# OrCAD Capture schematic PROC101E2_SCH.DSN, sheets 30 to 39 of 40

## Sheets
30 19. TEST AUTOMATION: size C; title: TEST AUTOMATION
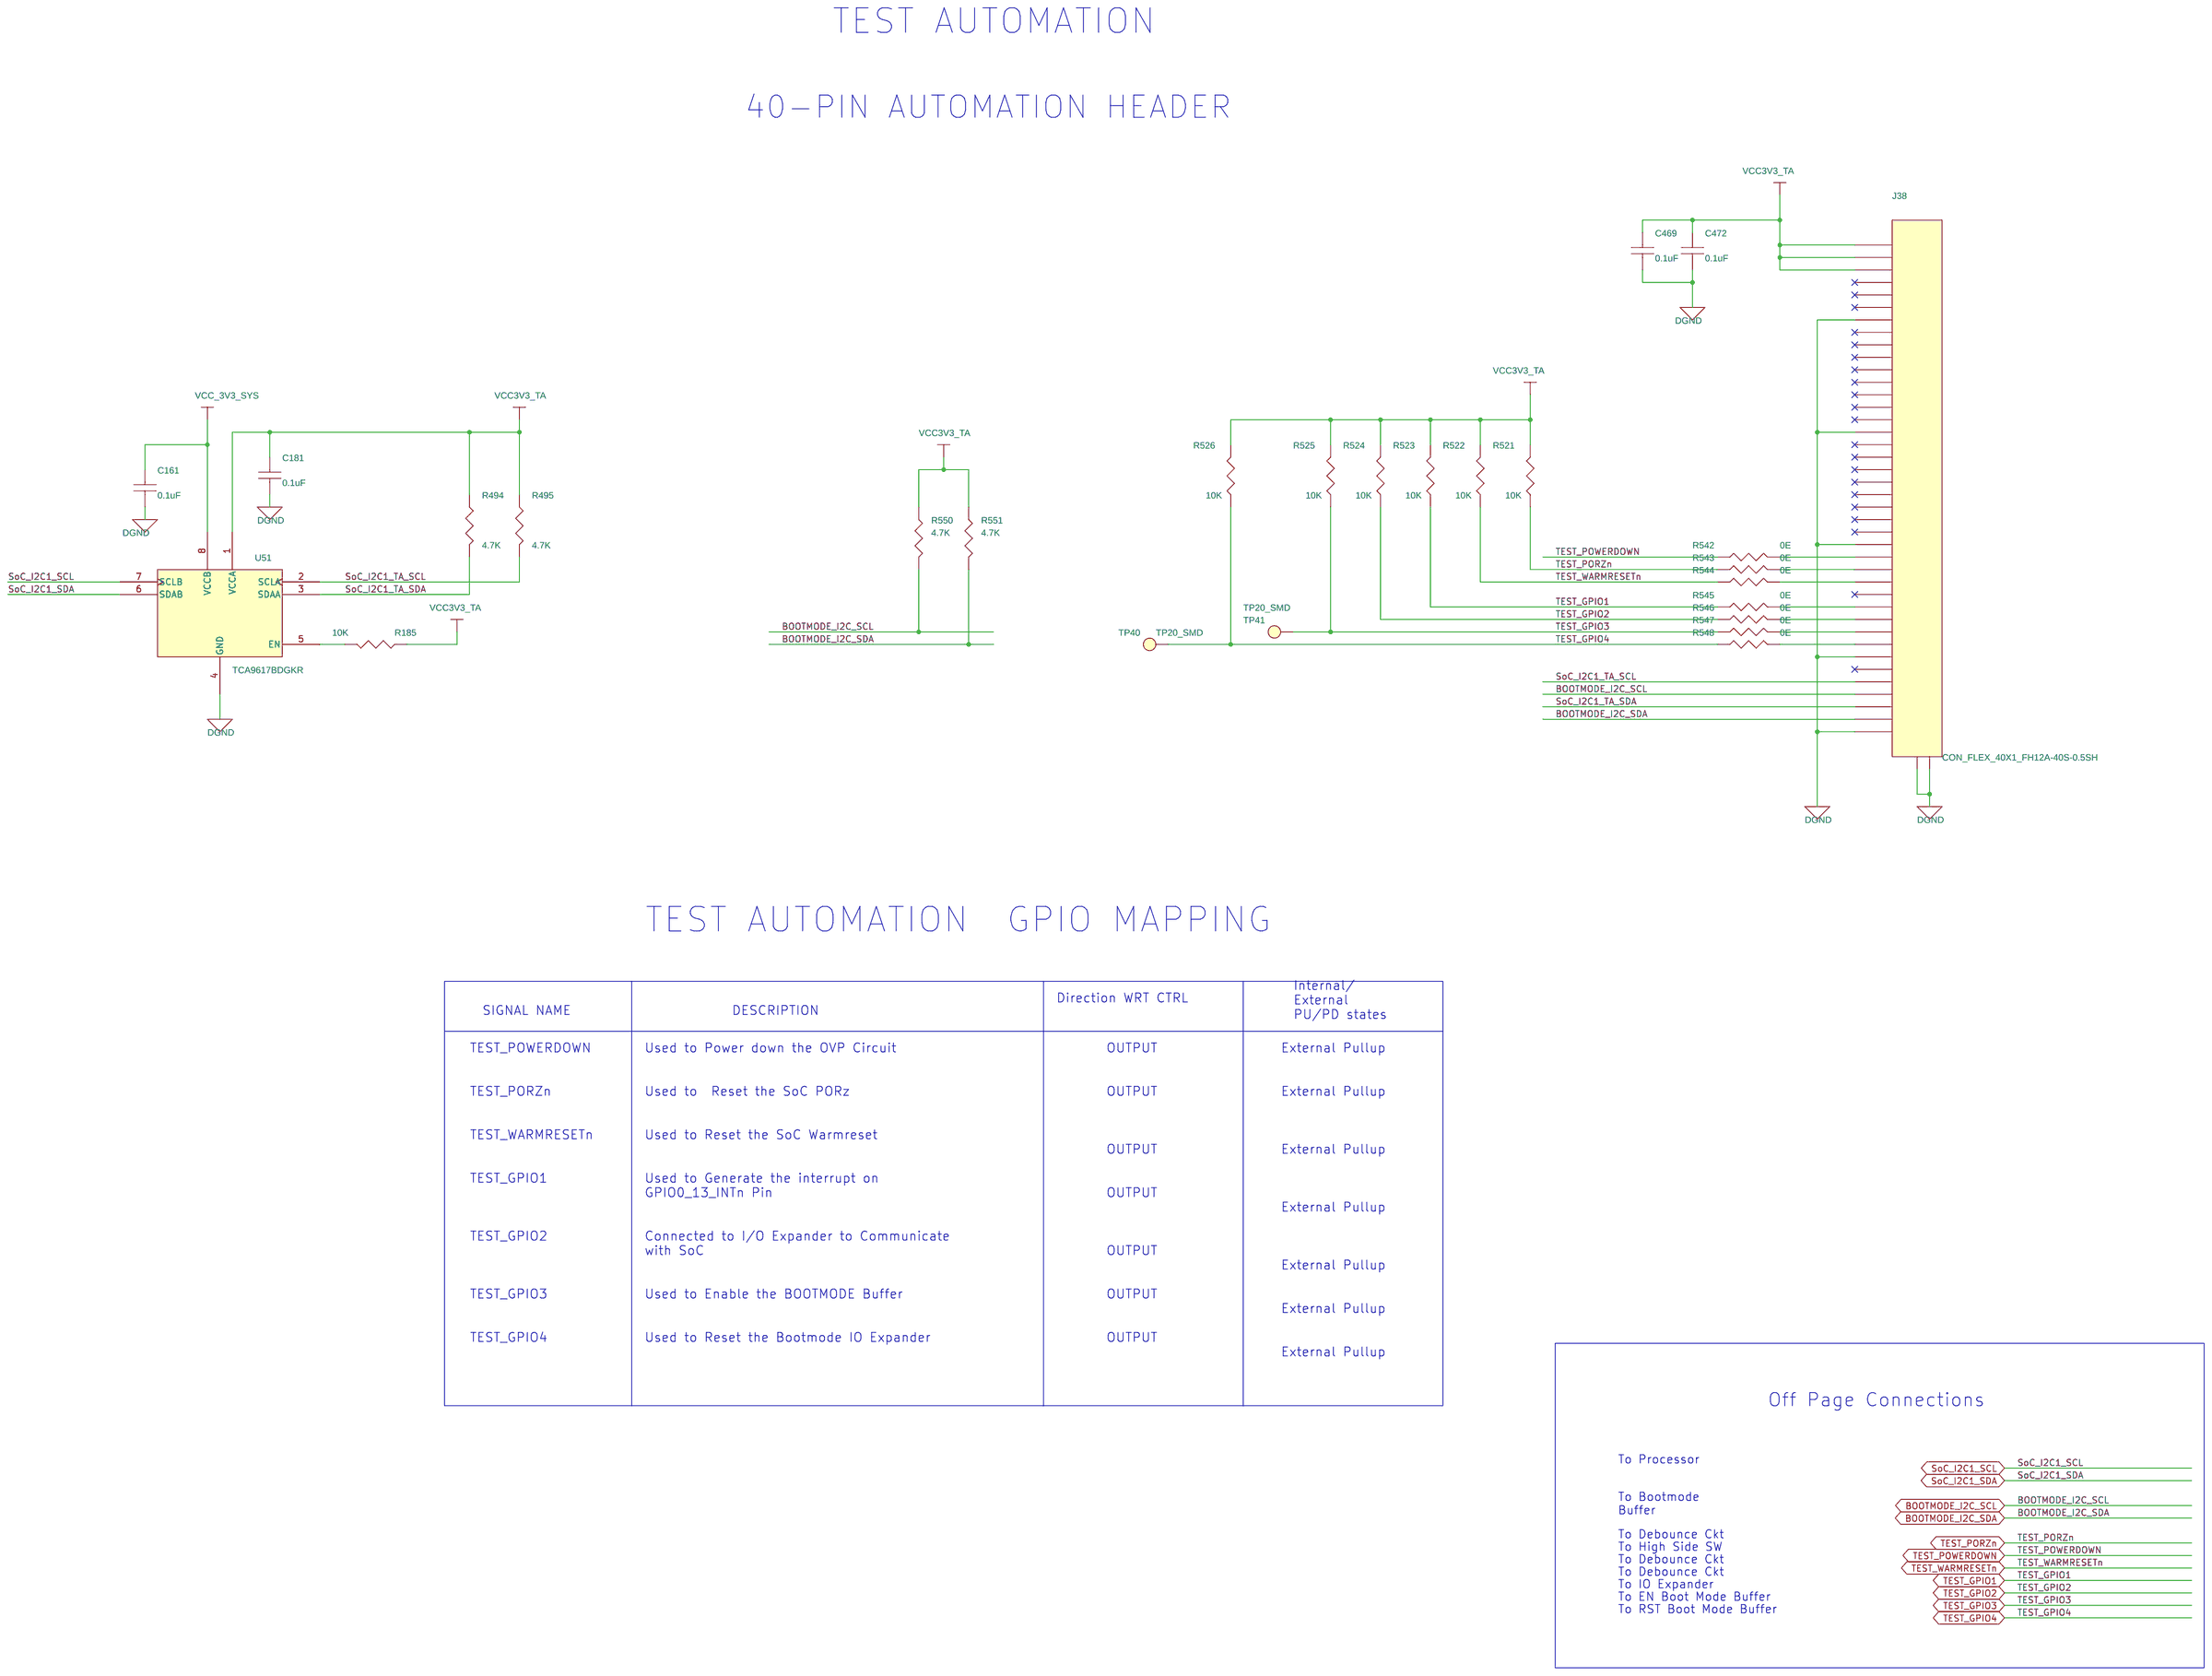
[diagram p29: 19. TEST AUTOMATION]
31 40. HARDWARE SCHEMATICS: title: HARDWARE SCHEMATICS
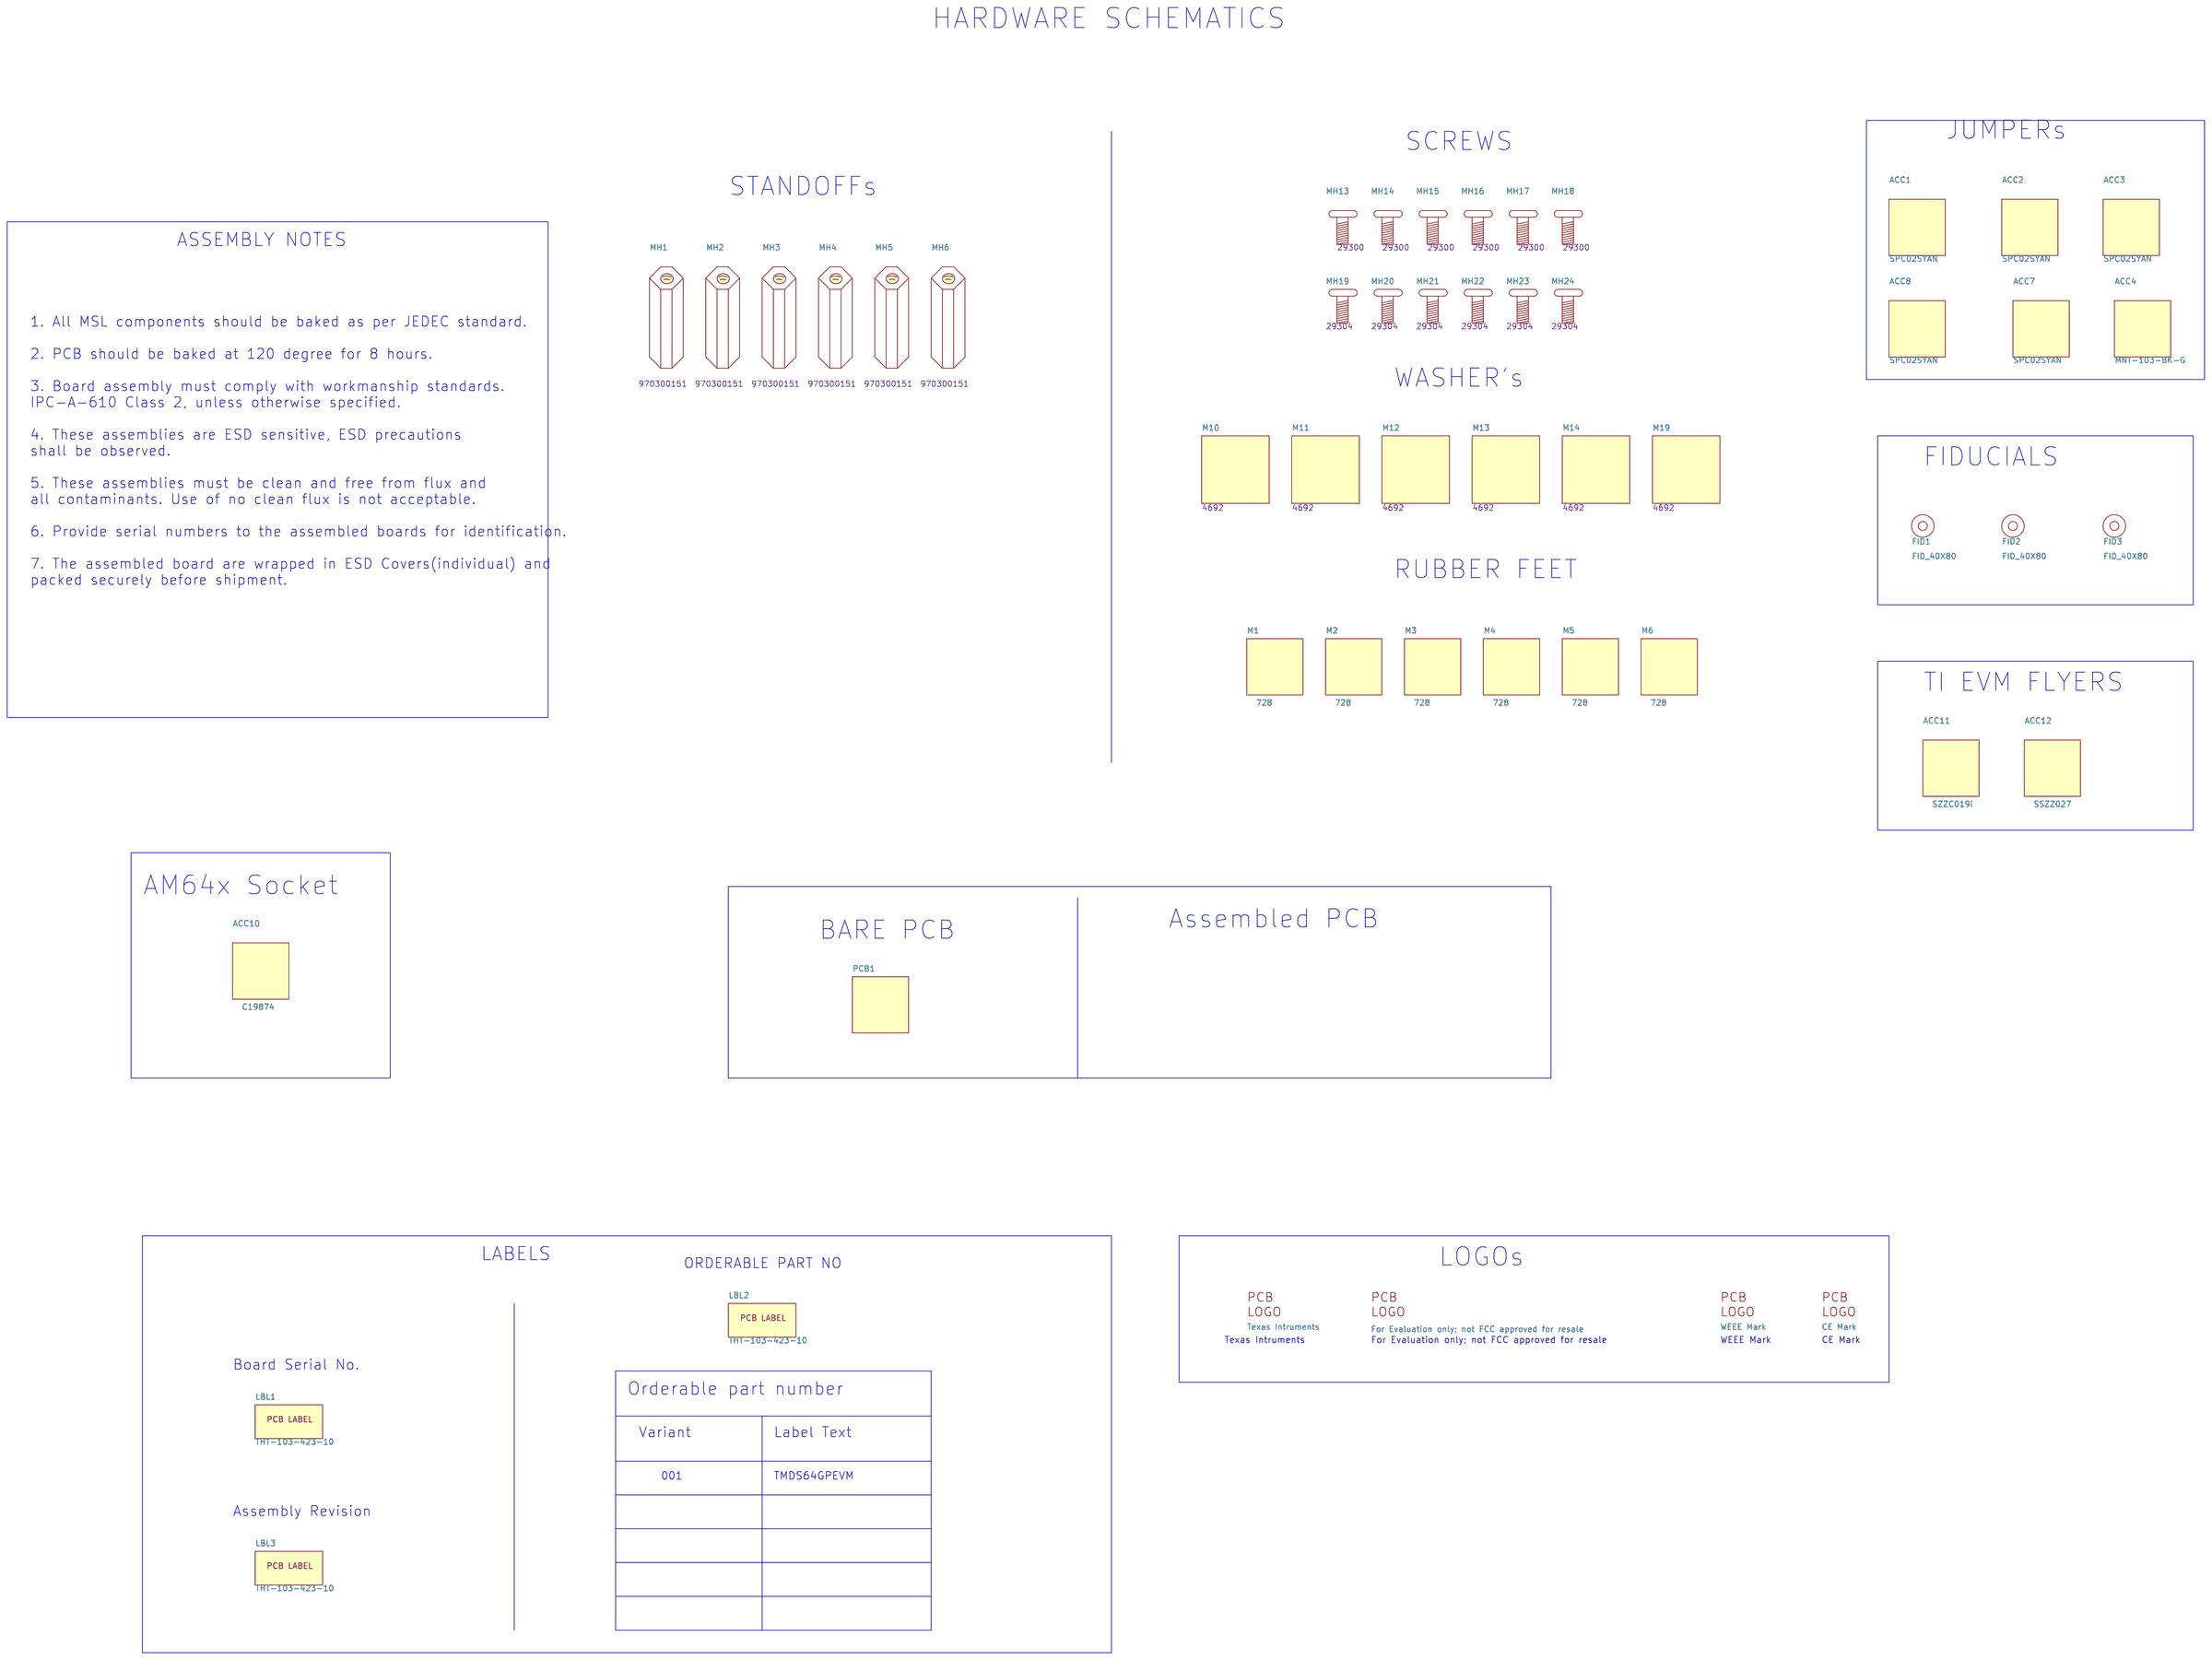
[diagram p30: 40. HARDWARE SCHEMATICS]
32 07. GPIO MAPPING TABLE: title: GPIO  MAPPING TABLE
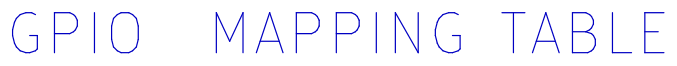
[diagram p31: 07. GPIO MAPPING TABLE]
33 08. I2C TREE: title: I2C TREE
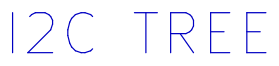
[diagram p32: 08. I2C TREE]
34 06. POWER SEQUENCE: title: POWER SEQUENCE
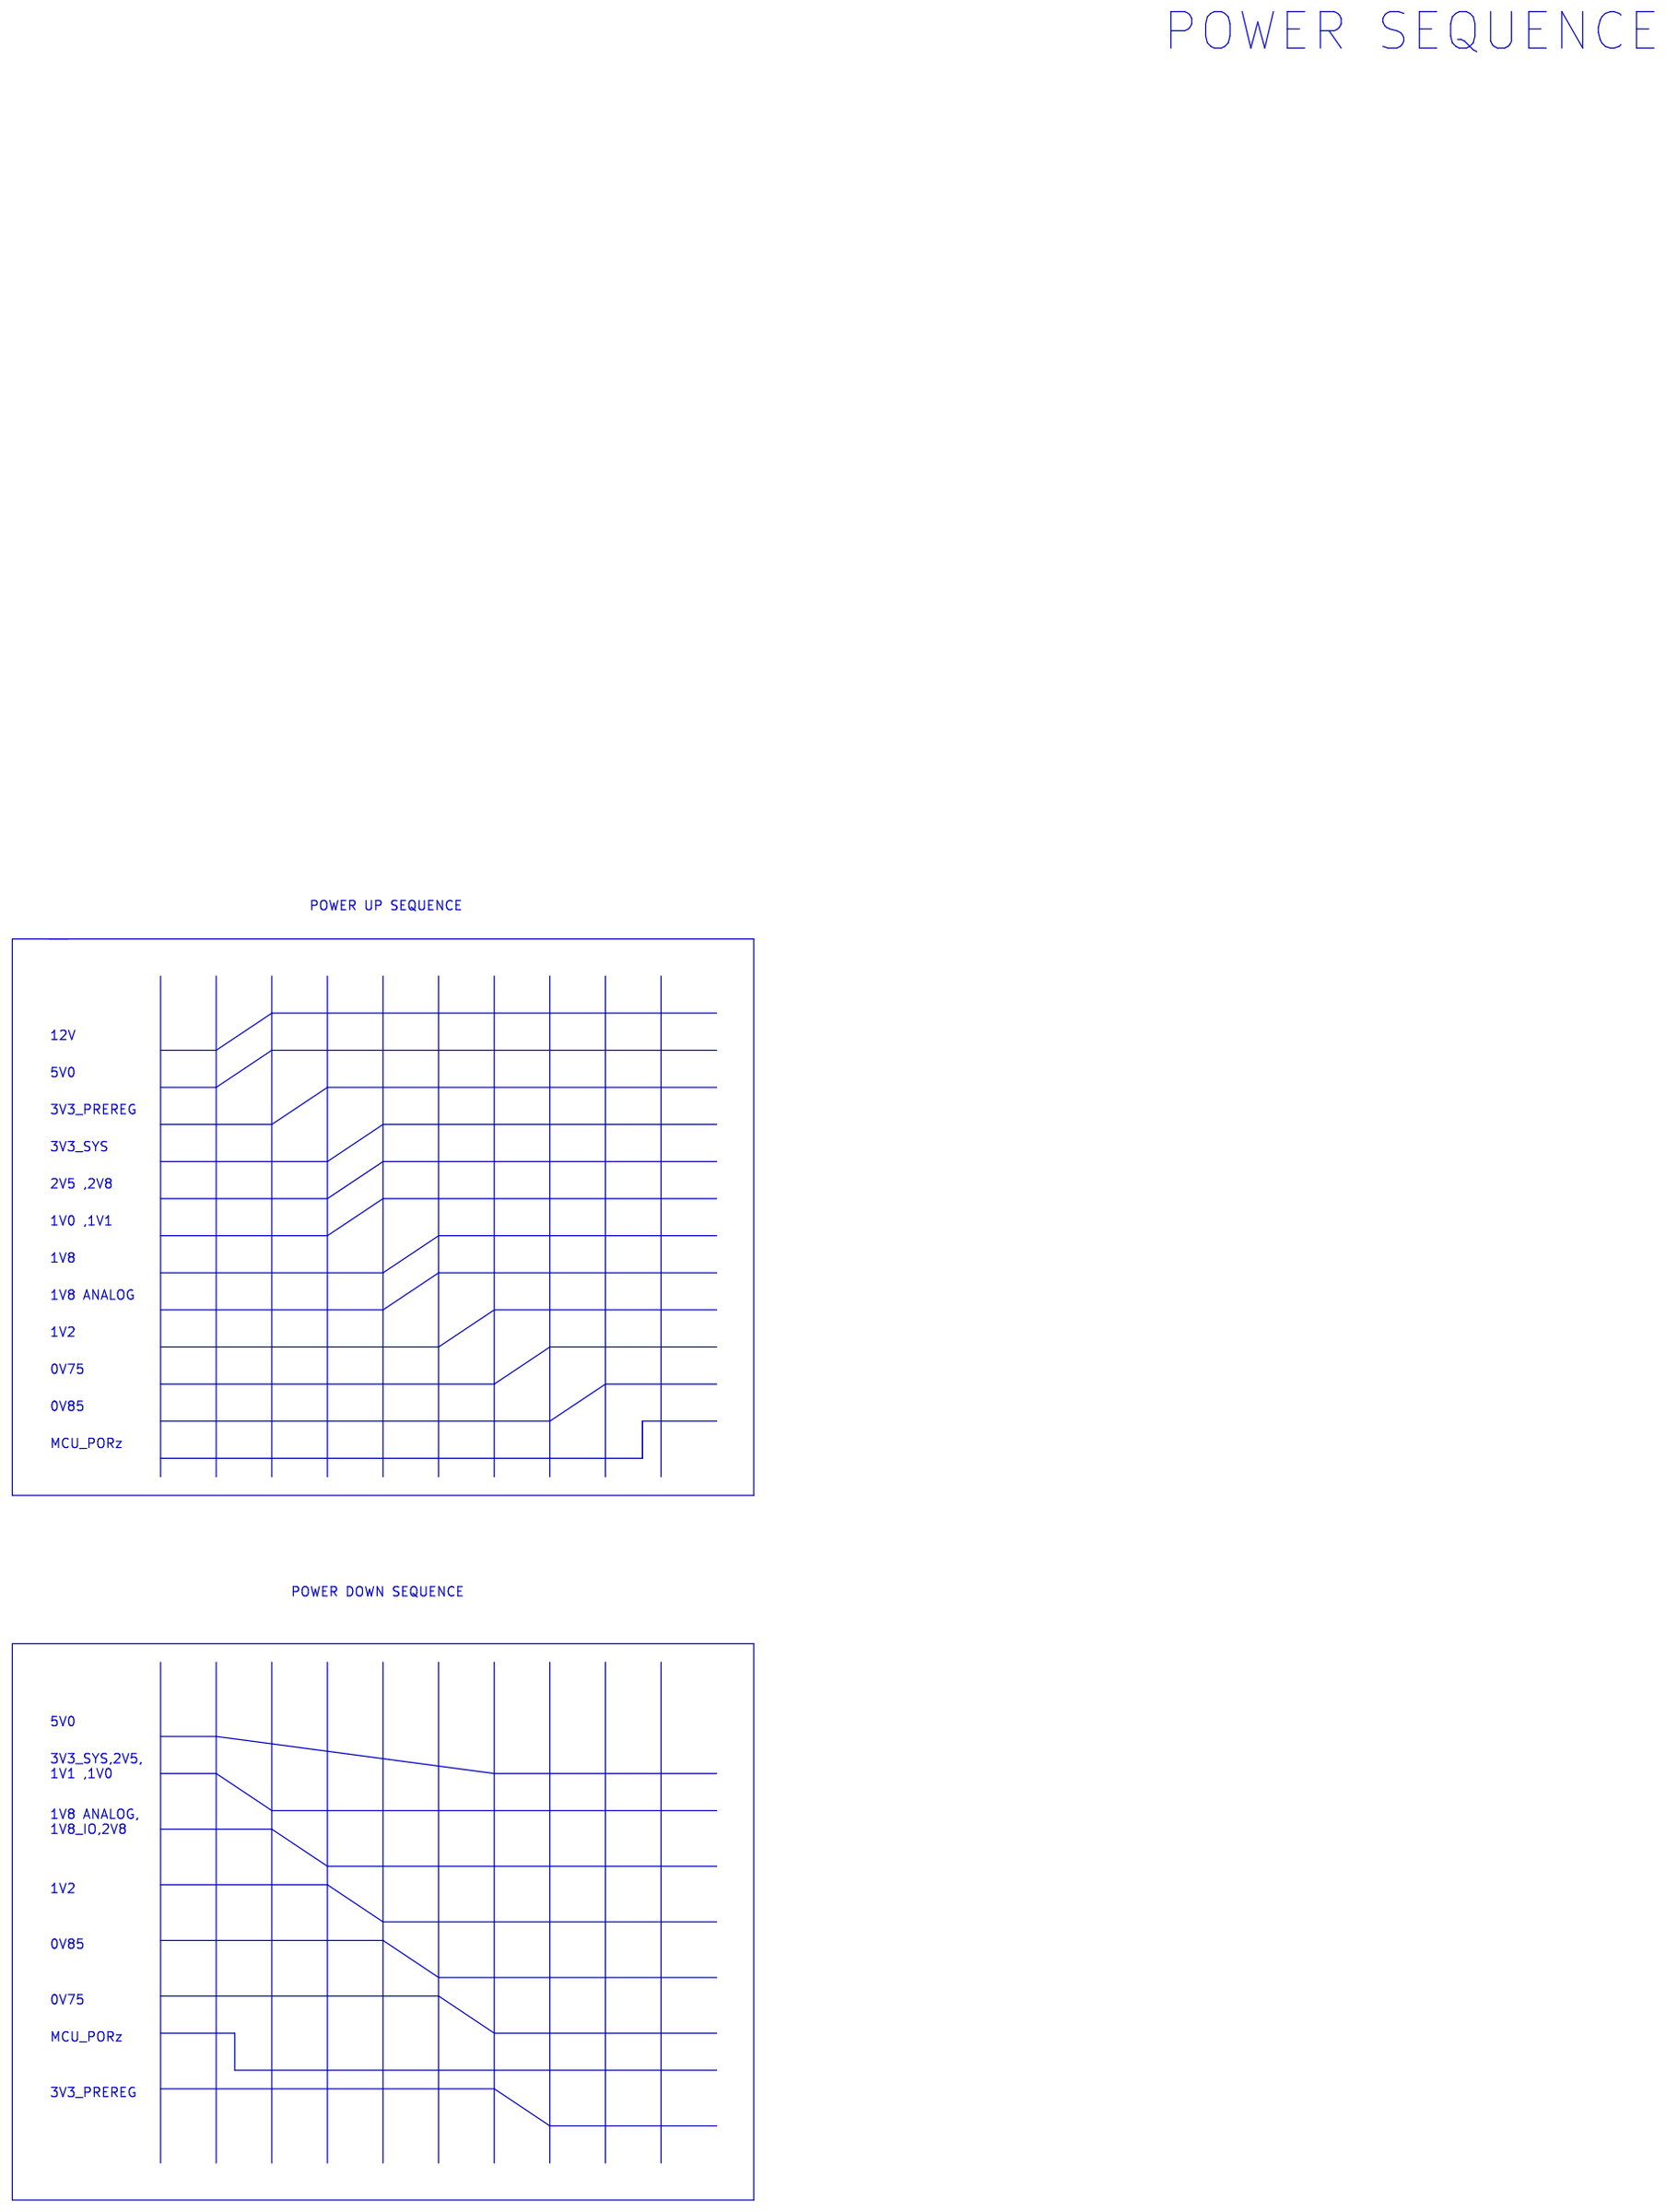
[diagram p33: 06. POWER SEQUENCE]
35 05. POWER FLOW DIAGRAM: title: POWER FLOW DIAGRAM
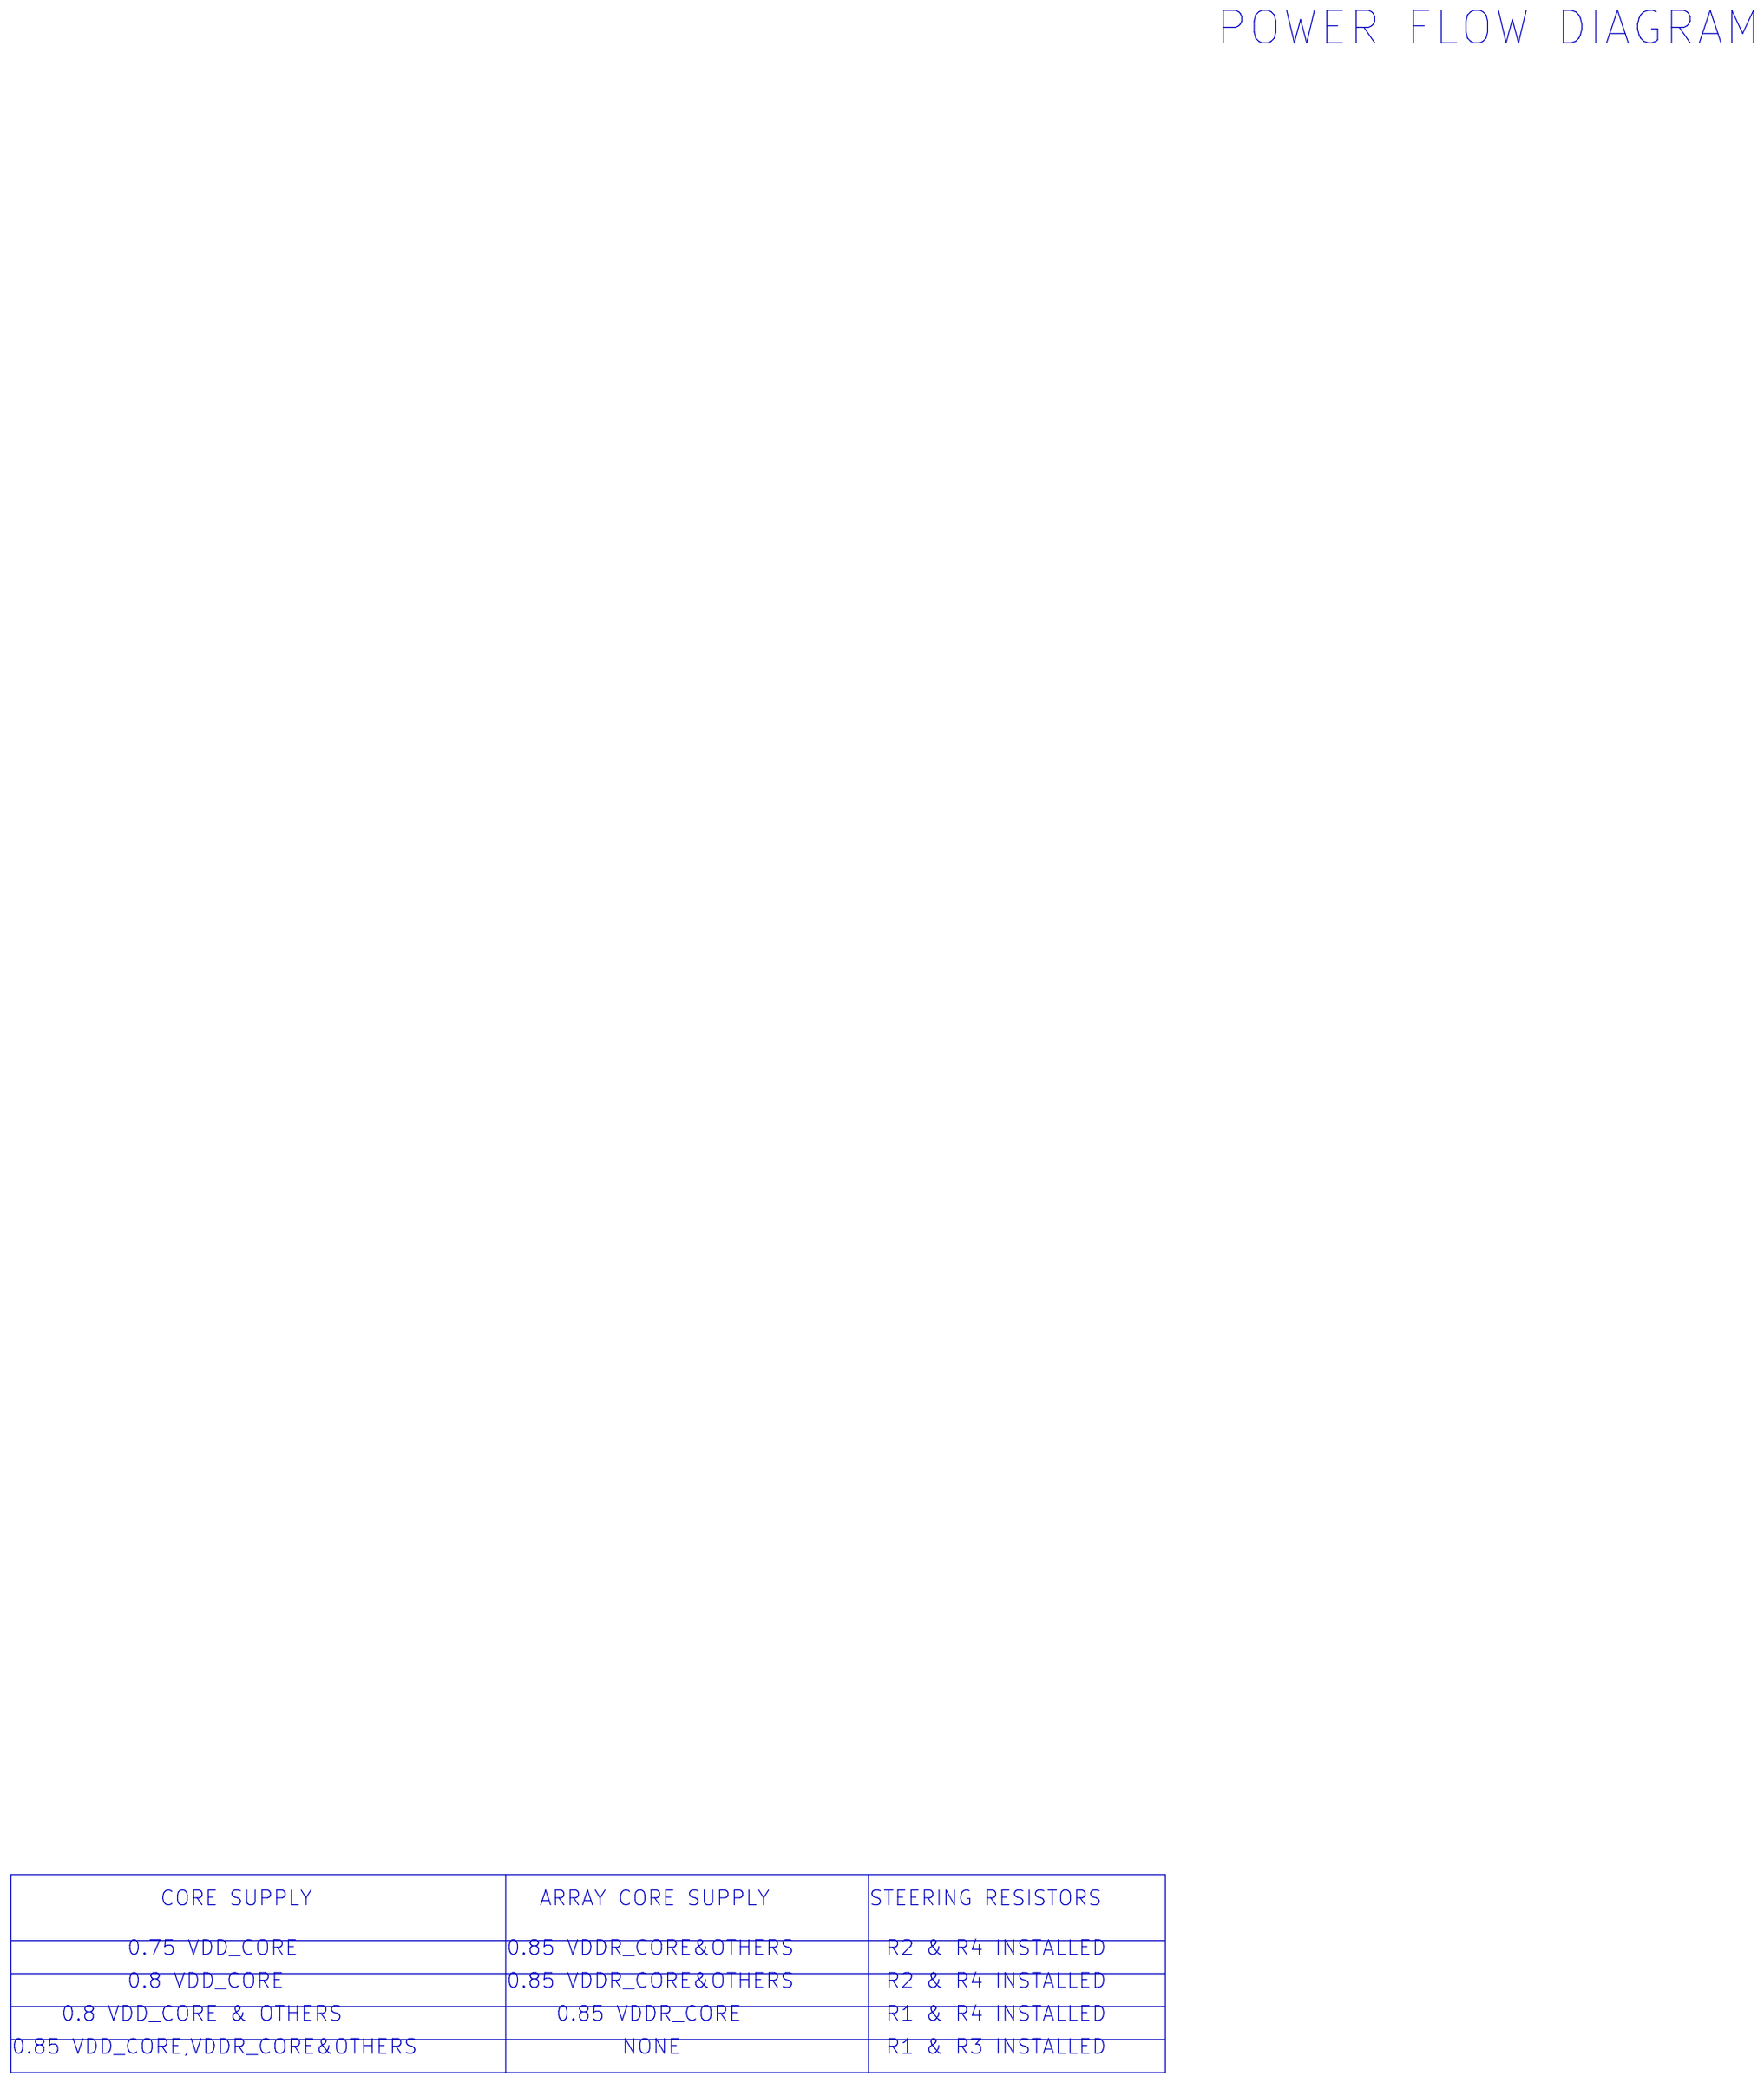
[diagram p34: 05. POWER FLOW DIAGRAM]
36 03.BLOCK_DIAGRAM_AM64x_EVM: title: BLOCK DIAGRAM_CP BOARD
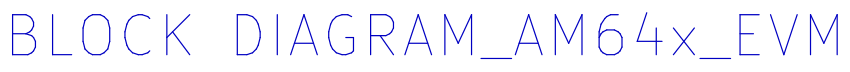
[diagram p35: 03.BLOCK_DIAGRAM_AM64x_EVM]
37 01. TABLE OF CONTENTS: title: TABLE OF CONTENTS
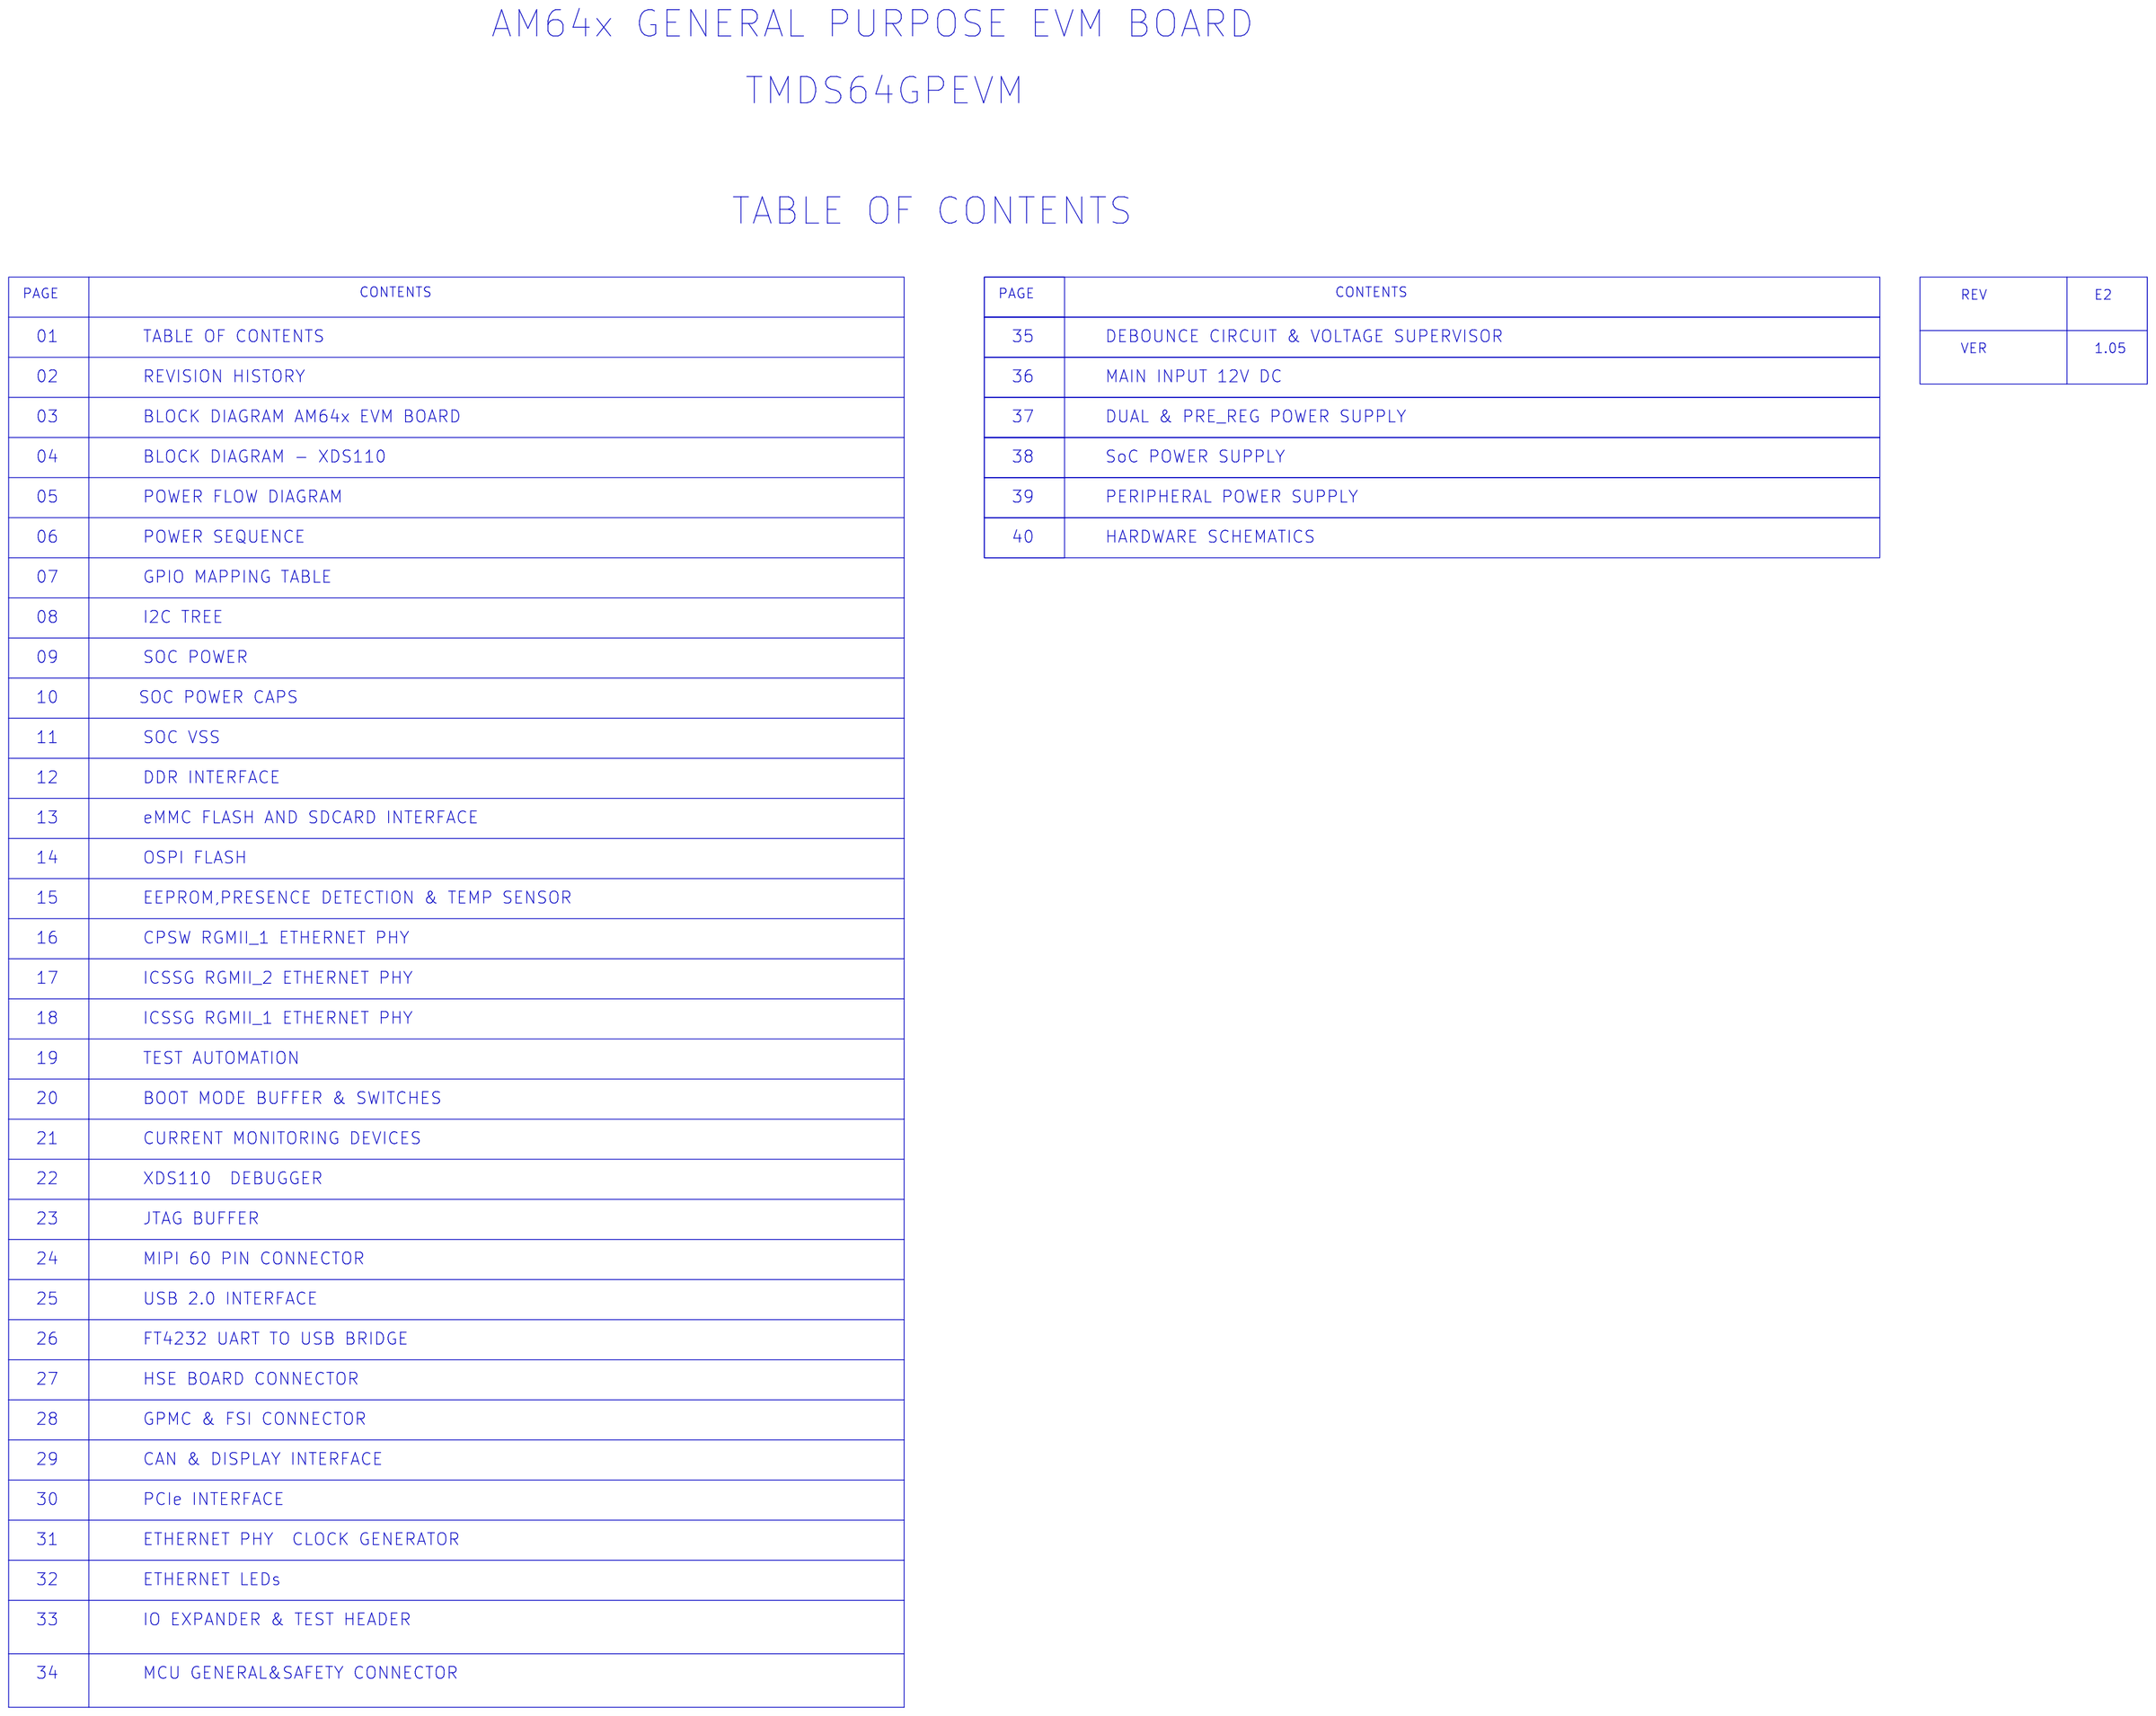
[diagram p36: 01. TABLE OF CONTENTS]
38 02. REVISION HISTORY: title: REVISION HISTORY
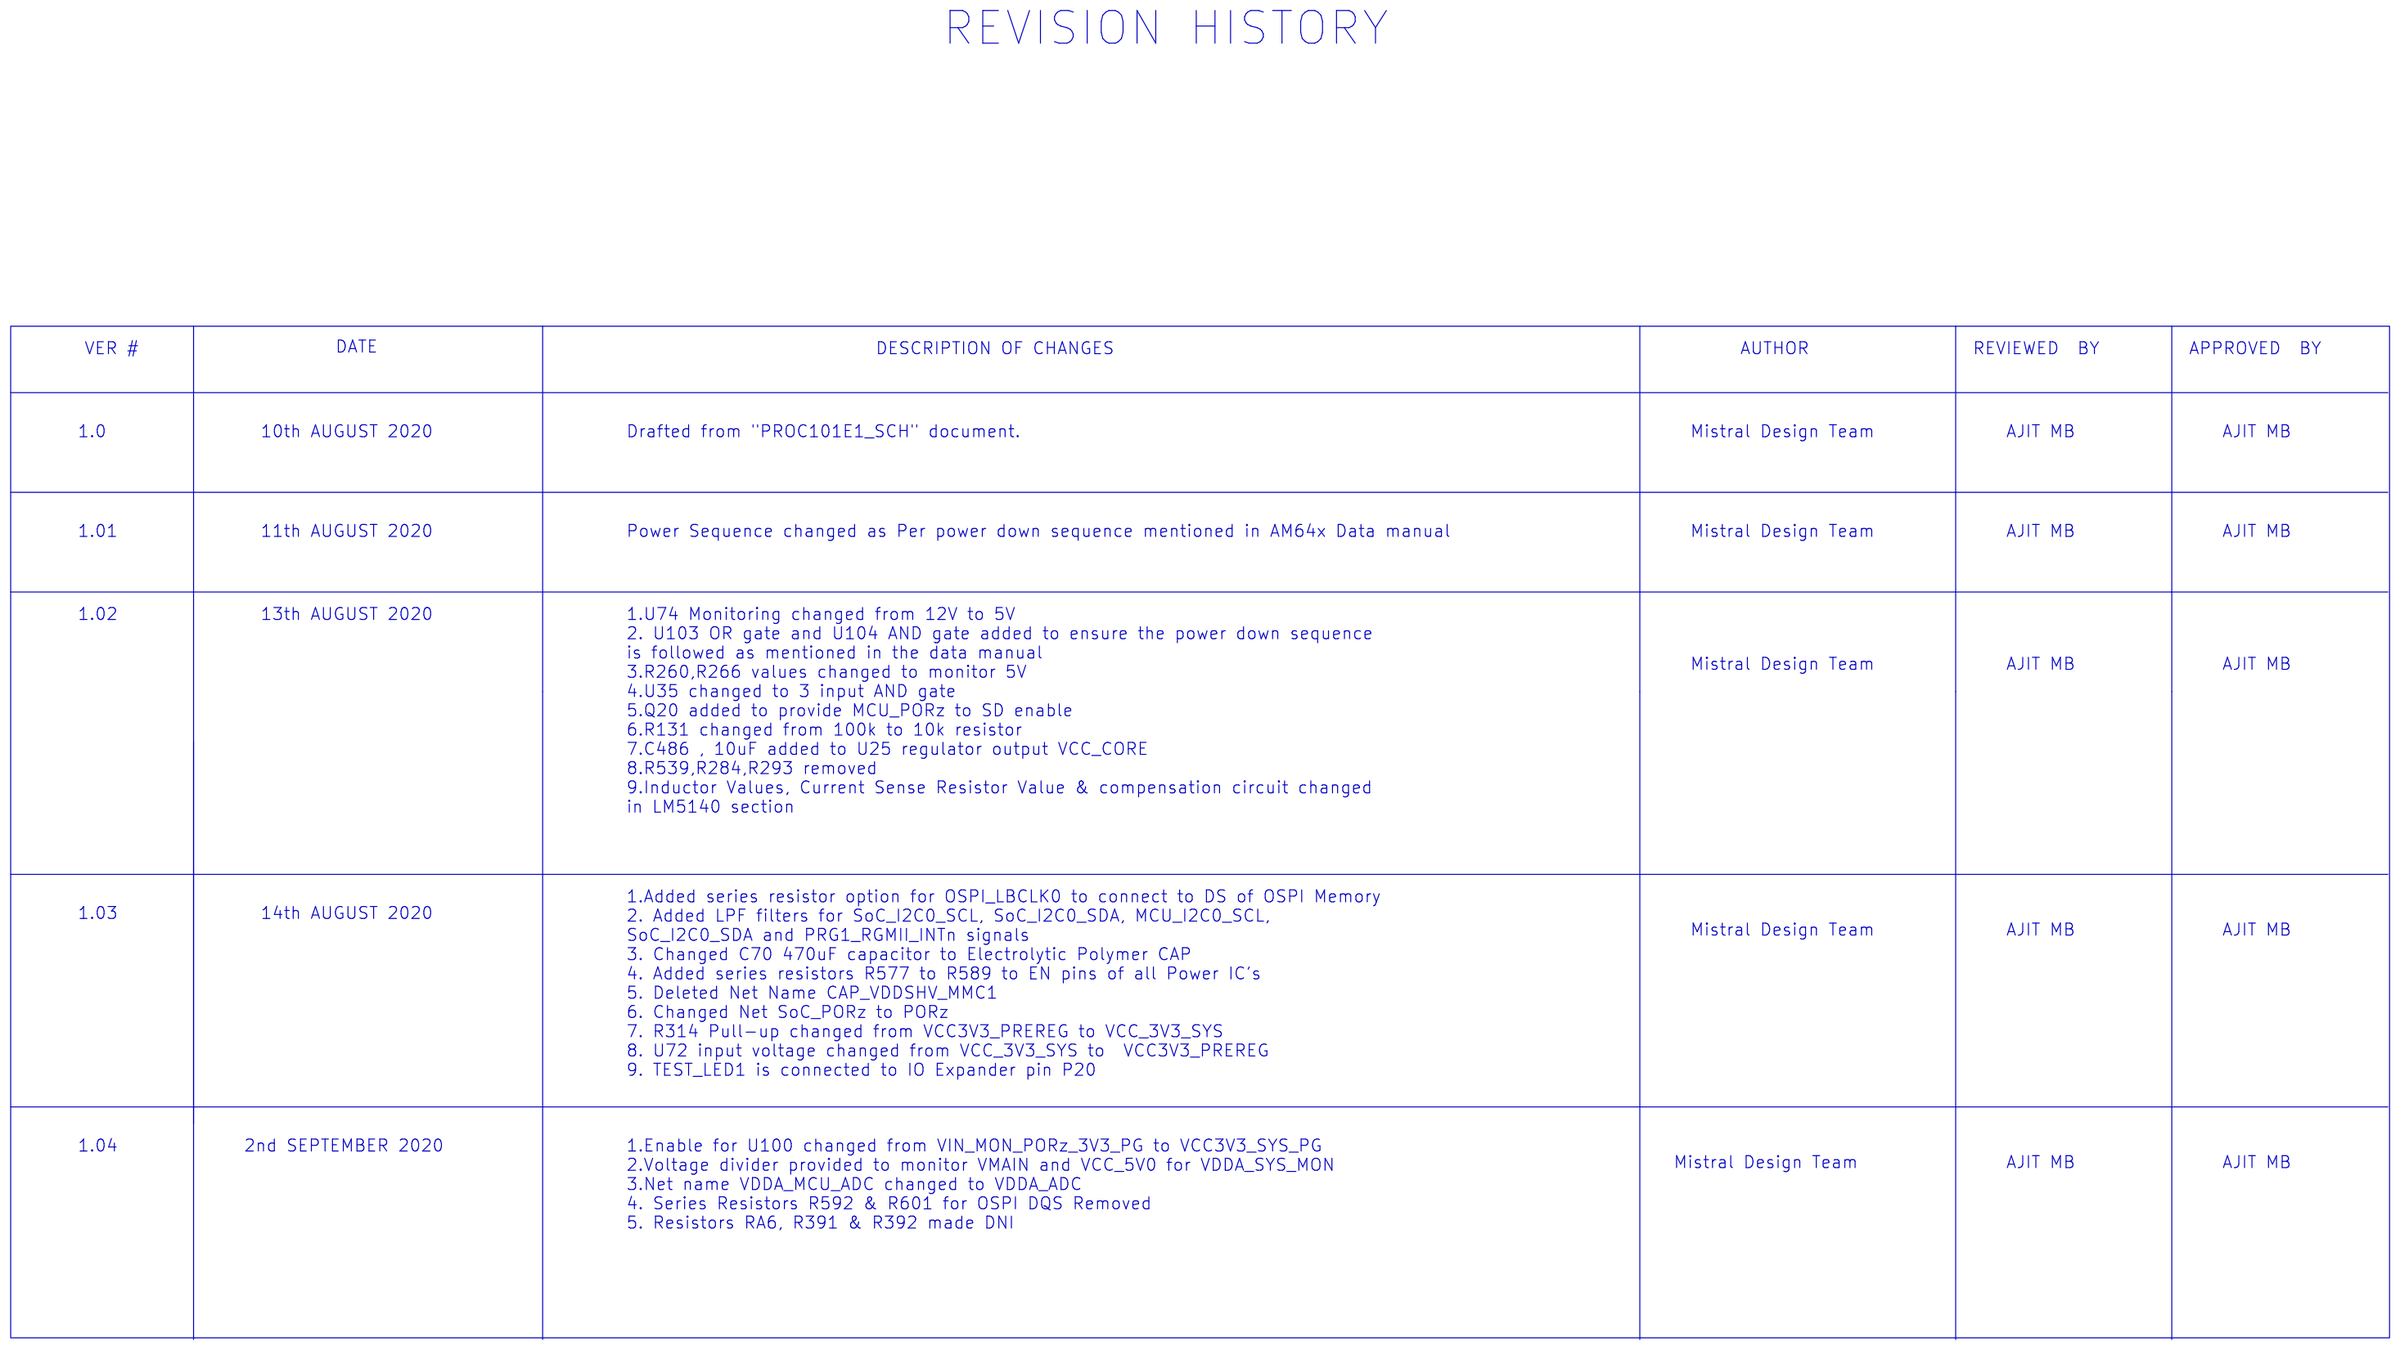
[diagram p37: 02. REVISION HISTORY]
39 17. ICSSG RGMII_2 ETHERNET PHY: size C; title: ICSSG1 RGMII_2 ETHERNET PHY
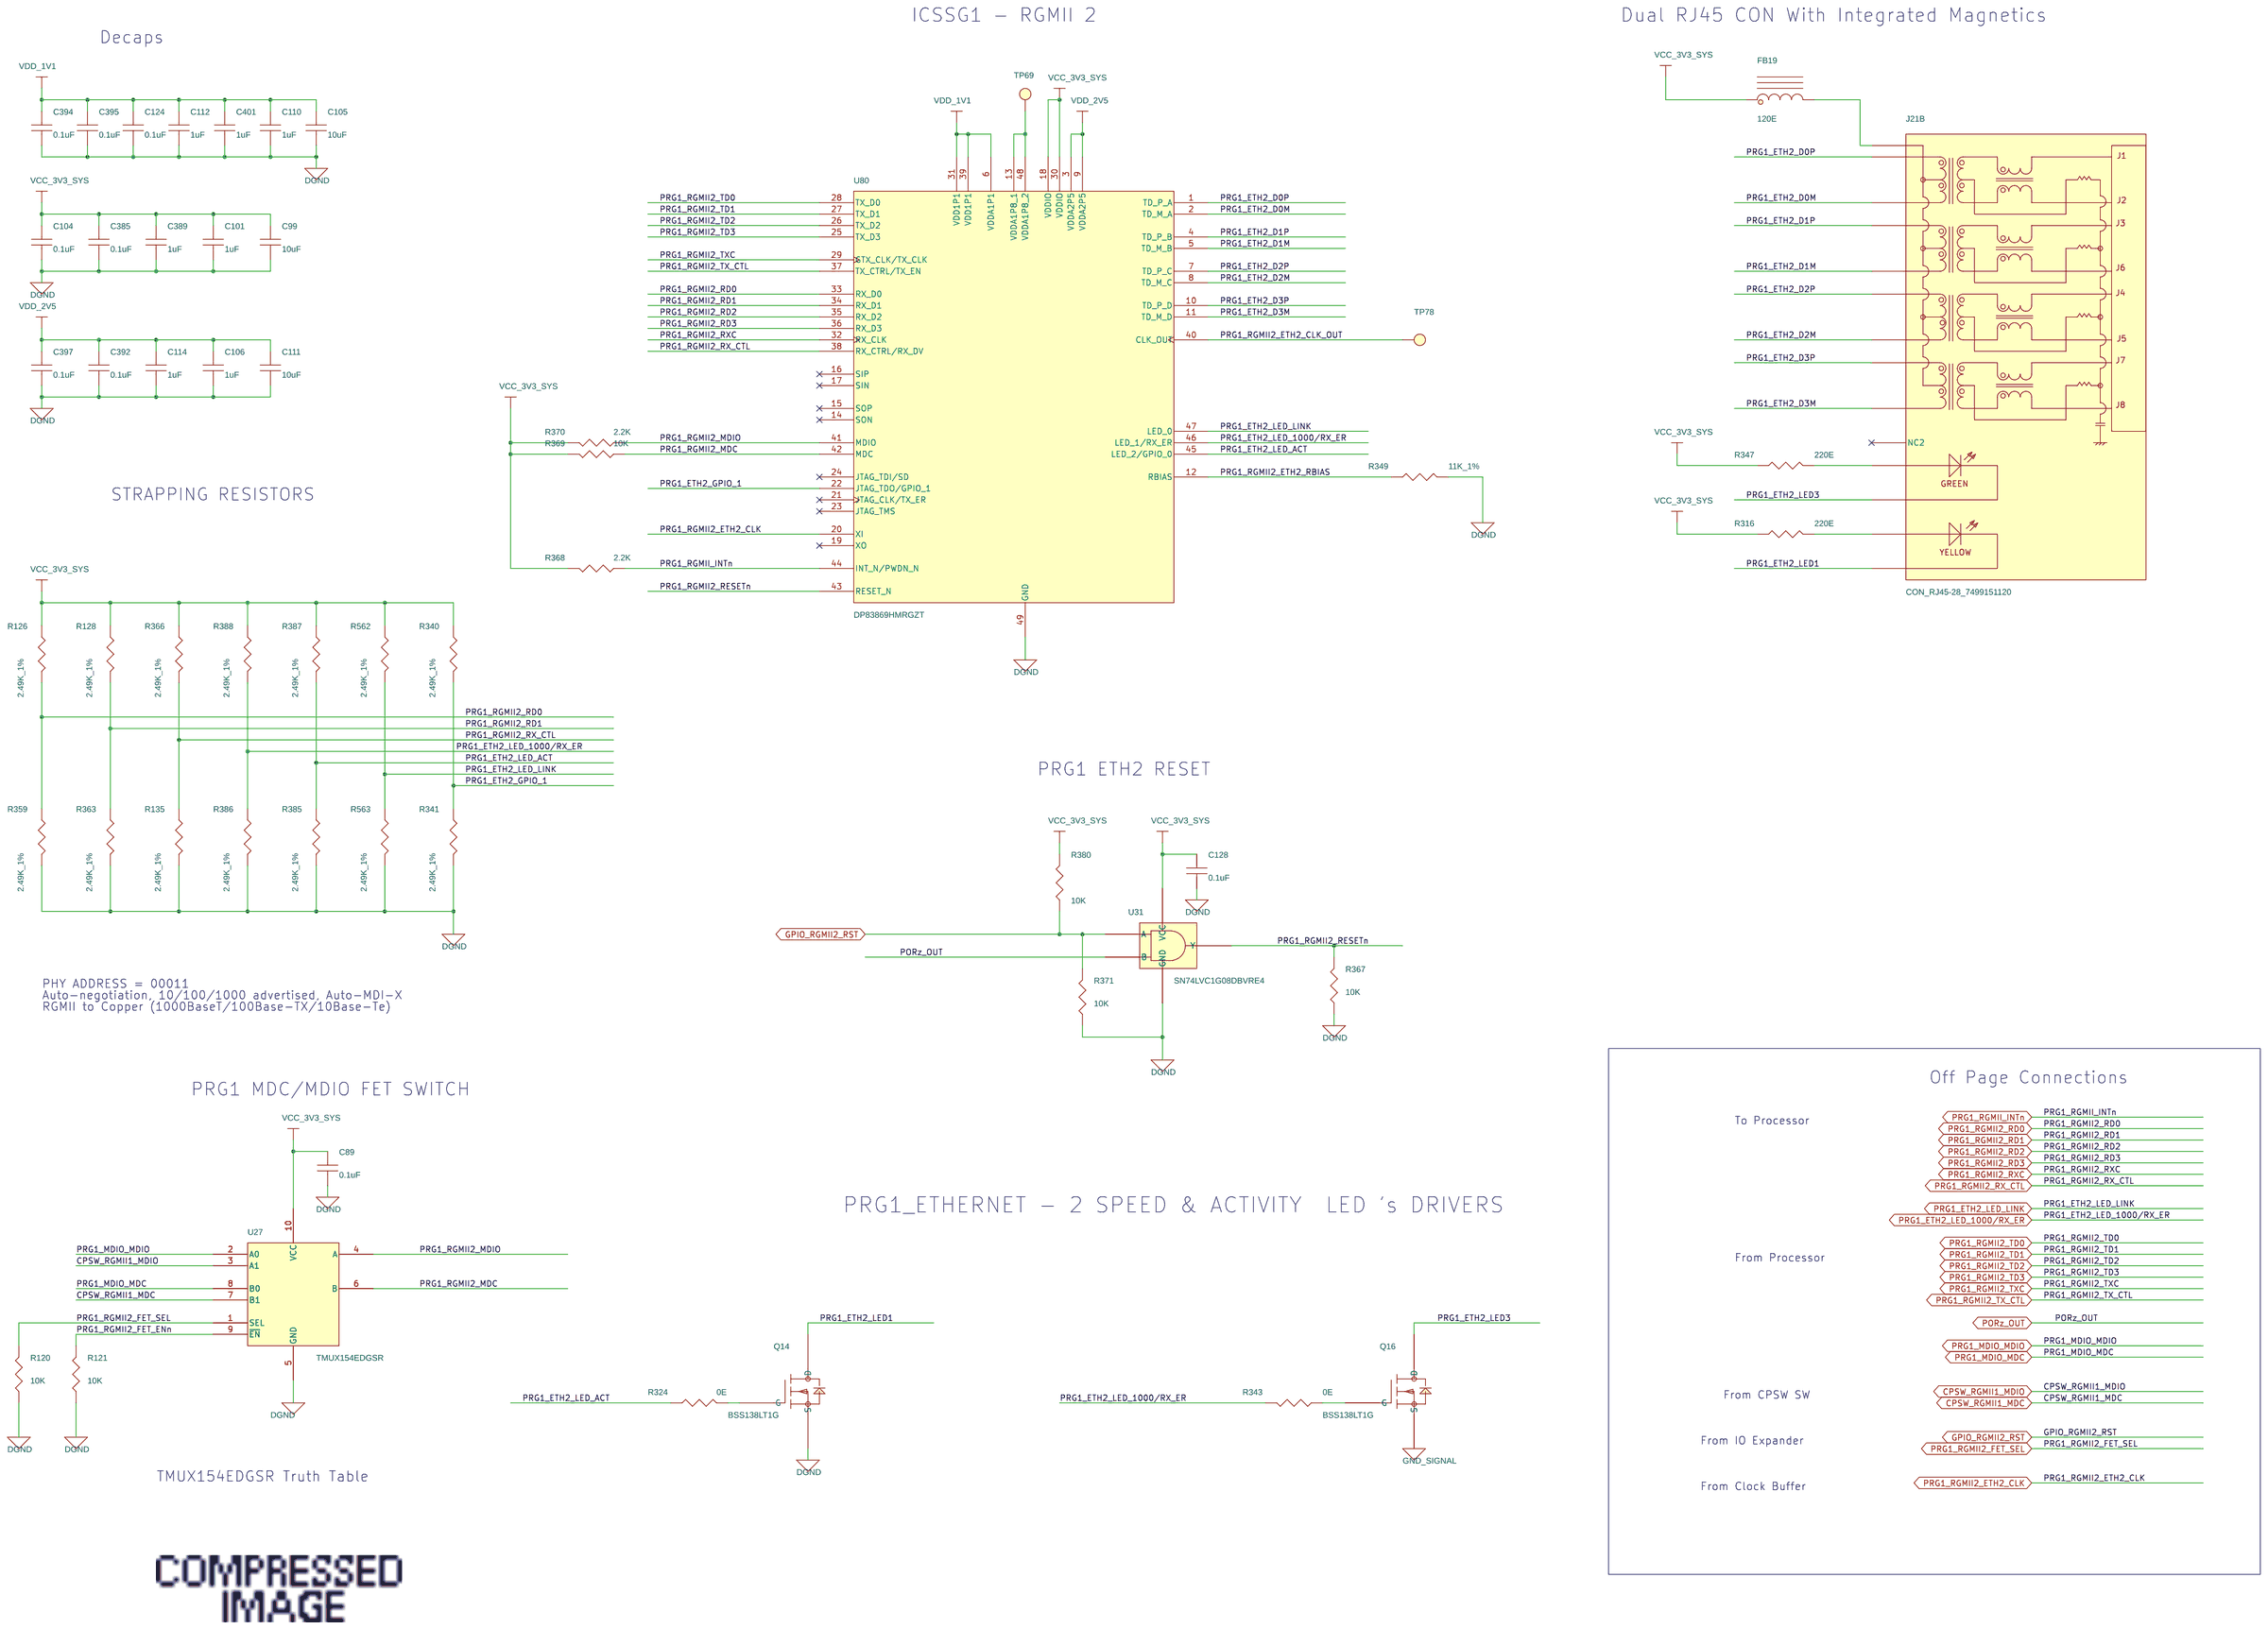
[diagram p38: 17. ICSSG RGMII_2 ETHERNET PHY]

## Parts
sheet 17. ICSSG RGMII_2 ETHERNET PHY
C89  0.1uF  [CAP0402_0-75]
C99  10uF  [CAP0402_0-75]
C101  1uF  [CAP0402_0-75]
C104  0.1uF  [CAP0402_0-75]
C105  10uF  [CAP0402_0-75]
C106  1uF  [CAP0402_0-75]
C110  1uF  [CAP0402_0-75]
C111  10uF  [CAP0402_0-75]
C112  1uF  [CAP0402_0-75]
C114  1uF  [CAP0402_0-75]
C124  0.1uF  [CAP0402_0-75]
C128  0.1uF  [CAP0402_0-75]
C385  0.1uF  [CAP0402_0-75]
C389  1uF  [CAP0402_0-75]
C392  0.1uF  [CAP0402_0-75]
C394  0.1uF  [CAP0402_0-75]
C395  0.1uF  [CAP0402_0-75]
C397  0.1uF  [CAP0402_0-75]
C401  1uF  [CAP0402_0-75]
FB19  120E  [IND0603_1]
J21  CON_RJ45-28_7499151120  [CON_RJ45-28_7499151120_S_R_T_25-7]  (sections A,B)
Q14  BSS138LT1G  [SOT23-123_1-2]
Q16  BSS138LT1G  [SOT23-123_1-2]
R120  10K  [RES0402_0-5]
R121  10K  [RES0402_0-5]
R126  2.49K_1%  [RES0402_0-5]
R128  2.49K_1%  [RES0402_0-5]
R135  2.49K_1%  [RES0402_0-5]
R316  220E  [RES0402_0-5]
R324  0E  [RES0402_0-5]
R340  2.49K_1%  [RES0402_0-5]
R341  2.49K_1%  [RES0402_0-5]
R343  0E  [RES0402_0-5]
R347  220E  [RES0402_0-5]
R349  11K_1%  [RES0402_0-5]
R359  2.49K_1%  [RES0402_0-5]
R363  2.49K_1%  [RES0402_0-5]
R366  2.49K_1%  [RES0402_0-5]
R367  10K  [RES0402_0-5]
R368  2.2K  [RES0402_0-5]
R369  10K  [RES0402_0-5]
R370  2.2K  [RES0402_0-5]
R371  10K  [RES0402_0-5]
R380  10K  [RES0402_0-5]
R385  2.49K_1%  [RES0402_0-5]
R386  2.49K_1%  [RES0402_0-5]
R387  2.49K_1%  [RES0402_0-5]
R388  2.49K_1%  [RES0402_0-5]
R562  2.49K_1%  [RES0402_0-5]
R563  2.49K_1%  [RES0402_0-5]
TP69  TP20_SMD  [TP20_SMD]
TP78  TP20_SMD  [TP20_SMD]
U27  TMUX154EDGSR  [MSOP10_19-68_120X120_1-1]
U31  SN74LVC1G08DBVRE4  [SOT23-5]
U80  DP83869HMRGZT  [QFN48_19-68_280X280_1_EP4-2]
sheet 19. TEST AUTOMATION
C161  0.1uF  [CAP0402_0-75]
C181  0.1uF  [CAP0402_0-75]
C469  0.1uF  [CAP0402_0-75]
C472  0.1uF  [CAP0402_0-75]
J38  CON_FLEX_40X1_FH12A-40S-0.5SH  [CON_FLEX40X1_FH12A_S_R_S]
R185  10K  [RES0402_0-5]
R494  4.7K  [RES0402_0-5]
R495  4.7K  [RES0402_0-5]
R521  10K  [RES0402_0-5]
R522  10K  [RES0402_0-5]
R523  10K  [RES0402_0-5]
R524  10K  [RES0402_0-5]
R525  10K  [RES0402_0-5]
R526  10K  [RES0402_0-5]
R542  0E  [RES0402_0-5]
R543  0E  [RES0402_0-5]
R544  0E  [RES0402_0-5]
R545  0E  [RES0402_0-5]
R546  0E  [RES0402_0-5]
R547  0E  [RES0402_0-5]
R548  0E  [RES0402_0-5]
R550  4.7K  [RES0402_0-5]
R551  4.7K  [RES0402_0-5]
TP40  TP20_SMD  [TP20_SMD]
TP41  TP20_SMD  [TP20_SMD]
U51  TCA9617BDGKR  [VSSOP8_25-59_120X120_1-1]
sheet 40. HARDWARE SCHEMATICS
1  PCB1
ACC1  SPC02SYAN  [NA]
ACC2  SPC02SYAN  [NA]
ACC3  SPC02SYAN  [NA]
ACC4  MNT-103-BK-G  [NA]
ACC7  SPC02SYAN  [NA]
ACC8  SPC02SYAN  [NA]
ACC10  C19874  [BGASKT441_C19874_1190X1190_11]
ACC11  SZZC019i  [NA]
ACC12  SSZZ027  [NA]
FID1  FID_40X80  [FID_40X80]
FID2  FID_40X80  [FID_40X80]
FID3  FID_40X80  [FID_40X80]
LBL1  THT-103-423-10  [NA]
LBL2  THT-103-423-10  [NA]
LBL3  THT-103-423-10  [NA]
Logo1  Texas Intruments  [TI_Stacked_Overlay_Small]
Logo2  For Evaluation only; not FCC approved for resale  [FCC_disclaimer]
Logo3  WEEE Mark  [TI_Stacked_Overlay_Small]
Logo4  CE Mark  [TI_Stacked_Overlay_Small]
M1  728  [NA]
M2  728  [NA]
M3  728  [NA]
M4  728  [NA]
M5  728  [NA]
M6  728  [NA]
M10  PLAIN WASHER_M3  [NA]
M11  PLAIN WASHER_M3  [NA]
M12  PLAIN WASHER_M3  [NA]
M13  PLAIN WASHER_M3  [NA]
M14  PLAIN WASHER_M3  [NA]
M19  PLAIN WASHER_M3  [NA]
MH1  HEX SPACER_M2.5 X 30  [NA]
MH2  HEX SPACER_M2.5 X 30  [NA]
MH3  HEX SPACER_M2.5 X 30  [NA]
MH4  HEX SPACER_M2.5 X 30  [NA]
MH5  HEX SPACER_M2.5 X 30  [NA]
MH6  HEX SPACER_M2.5 X 30  [NA]
MH13  PAN HEAD_M2.5 X 4  [NA]
MH14  PAN HEAD_M2.5 X 4  [NA]
MH15  PAN HEAD_M2.5 X 4  [NA]
MH16  PAN HEAD_M2.5 X 4  [NA]
MH17  PAN HEAD_M2.5 X 4  [NA]
MH18  PAN HEAD_M2.5 X 4  [NA]
MH19  PAN HEAD_M2.5 X 12  [NA]
MH20  PAN HEAD_M2.5 X 12  [NA]
MH21  PAN HEAD_M2.5 X 12  [NA]
MH22  PAN HEAD_M2.5 X 12  [NA]
MH23  PAN HEAD_M2.5 X 12  [NA]
MH24  PAN HEAD_M2.5 X 12  [NA]

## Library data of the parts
C89 C104 C124 C128 C161 C181 C385 C392 C394 C395 C397 C469 C472 = CAP: CAP CERAMIC 0.1uF 25V 20% X5R 0402; Alt_Mfr_name: YAGEO AMERICA; Alt_Mfr_part_number: CC0402KRX5R8BB104; Chkd/date: MANIRAJA/170820; Crtd /date: ALVY/170820; Custom_Duty: 15%; Customs_HS_Code: 85322990; Distributor_name: DIGIKEY; Distributor_part_number: 732-7495-1-ND; Footprint Path: Y:\MIS_DATABASE\Library\ALTIUM_TOOL\PCB_FOOTPRINTS\Altium_Footprint_Lib.PcbLib; Height: 0.55MM; Library Path: Y:\MIS_DATABASE\Library\ALTIUM_TOOL\SCHEMATICS_PARTS\MS_DISCRETE_Library.schlib; Mfr_name: WURTH ELECTRONICS; Mfr_part_number: 885012105018; Mistral Part No: 120020080003-R; Package: 0402; Part_type: CAPACITORS\CERAMIC; Project: AM64x_EVM_BRD; RoHS: RoHS; Temperature: -55°C+85°C; Tolerance: 20%; Voltage: 25V; Wattage: NA; Weight: 0.65mg; Datasheet: Y:\MIS_DATABASE\DATASHEETS\CAPACITORS\885012105018.PDF
C99 C105 C111 = CAP: CAP CERAMIC 10uF 10V 20% X5R 0402; Chkd/date: MANIRAJA/300520; Crtd /date: ALVY/260520; Custom_Duty: 15%; Customs_HS_Code: 85322990; Distributor_name: DIGIKEY; Distributor_part_number: 490-GRM155R61A106ME11DTR-ND; Footprint Path: Y:\MIS_DATABASE\Library\ALTIUM_TOOL\PCB_FOOTPRINTS\Altium_Footprint_Lib.PcbLib; Height: 0.55MM; Library Path: Y:\MIS_DATABASE\Library\ALTIUM_TOOL\SCHEMATICS_PARTS\MS_DISCRETE_Library.schlib; Mfr_name: MURATA; Mfr_part_number: GRM155R61A106ME11D; Mistral Part No: 120013110019-R; Package: 0402; Part_type: CAPACITORS\CERAMIC; Project: QCS610_NANOSOM; RoHS: RoHS; Temperature: -55°C+85°C; Tolerance: 20%; Voltage: 10V; Wattage: NA; Weight: 3.1mg; Datasheet: Y:\MIS_DATABASE\DATASHEETS\CAPACITORS\MURATA-GXX-SER_NOV17.PDF
C101 C106 C110 C112 C114 C389 C401 = CAP: CAP CERAMIC 1uF 10V 20% X5R 0402; Chkd/date: MANIRAJA/210820; Crtd /date: ALVY/190820; Custom_Duty: 15%; Customs_HS_Code: 85322990; Distributor_name: DIGIKEY; Distributor_part_number: 732-7489-1-ND; Footprint Path: Y:\MIS_DATABASE\Library\ALTIUM_TOOL\PCB_FOOTPRINTS\Altium_Footprint_Lib.PcbLib; Height: 0.55MM; Library Path: Y:\MIS_DATABASE\Library\ALTIUM_TOOL\SCHEMATICS_PARTS\MS_DISCRETE_Library.schlib; Mfr_name: WURTH ELECTRONICS; Mfr_part_number: 885012105012; Mistral Part No: 120020080009-R; Package: 0402; Part_type: CAPACITORS\CERAMIC; Project: AM64x_EVM_BRD; RoHS: RoHS; Temperature: -55°C+85°C; Tolerance: 20%; Voltage: 10V; Wattage: NA; Weight: 0.65mg; Datasheet: Y:\MIS_DATABASE\DATASHEETS\CAPACITORS\885012105012.PDF
FB19 = INDUCTOR_FERRITE: IND FERRITE BEAD CHIP 120E 2A 0603; Assembly: DNI; Chkd/date: MANIRAJA/180820; Crtd /date: ALVY/180820; Custom_Duty: 24%; Customs_HS_Code: 85437099; Distributor_name: DIGIKEY; Distributor_part_number: 732-782631141CT-ND; Footprint Path: Y:\MIS_DATABASE\Library\ALTIUM_TOOL\PCB_FOOTPRINTS\Altium_Footprint_Lib.PcbLib; Height: 1.00MM; Library Path: Y:\MIS_DATABASE\Library\ALTIUM_TOOL\SCHEMATICS_PARTS\MS_FILTER_Library.schlib; Mfr_name: WURTH ELECTRONICS; Mfr_part_number: 782631141; Mistral Part No: 130020080015-R; Package: 0603; Part_type: INDUCTOR; Project: AM64x_EVM_BRD; RoHS: RoHS; Temperature: -55°C+125°C; Tolerance: 25%; Voltage: NA; Wattage: NA; Weight: NA; Datasheet: Y:\MIS_DATABASE\DATASHEETS\DISCRETES\INDUCTORS\782631141.PDF
J21 = CON_RJ45-28_7499151120: CON JACK RJ45 STACKED 28POS FEMALE RT TH; Chkd/date: MANIRAJA/101118; Crtd /date: ALVY/091118; Custom_Duty: 24%; Customs_HS_Code: 85369090; Distributor_name: DIGIKEY; Distributor_part_number: 732-4961-5-ND; Footprint Path: Y:\MIS_DATABASE\Library\ALTIUM_TOOL\PCB_FOOTPRINTS\Altium_Footprint_Lib.PcbLib; Height: 25.63MM; Library Path: Y:\MIS_DATABASE\Library\ALTIUM_TOOL\SCHEMATICS_PARTS\MS_CONNECTOR_Library.schlib; Mfr_name: WURTH ELECTRONICS; Mfr_part_number: 7499151120; Mistral Part No: 150018110012-R; Package: THRU HOLE; Part_type: CONNECTOR\JACK; Project: NPOL_32SC; RoHS: RoHS; Temperature: -40°C+85°C; Tolerance: NA; Voltage: NA; Wattage: NA; Weight: NA; Datasheet: Y:\MIS_DATABASE\DATASHEETS\CONNECTORS\7499151120.PDF
Q14 Q16 = MOSFET_BSS138LT1G: IC MOSFET N-CHANNEL 50V 200mA SOT23-3; Chkd/date: MANIRAJA/250219; Crtd /date: JEBRAN/060416; Custom_Duty: 15%; Customs_HS_Code: 85423100; Distributor_name: DIGIKEY; Distributor_part_number: BSS138LT1GOSCT-ND; Footprint Path: Y:\MIS_DATABASE\Library\ALTIUM_TOOL\PCB_FOOTPRINTS\Altium_Footprint_Lib.PcbLib; Height: 1.11MM; Library Path: Y:\MIS_DATABASE\Library\ALTIUM_TOOL\SCHEMATICS_PARTS\MS_MOSFET_Library.schlib; Library Ref: MOSFET_BSS138W; Mfr_name: ON SEMICONDUCTOR; Mistral Part No: 142016040001-R; Package: SOT23-3; Part_type: ICS\POWER\MOSFET; Project: LRDE_ABCM; RoHS: RoHS; Temperature: -55°C+150°C; Tolerance: NA; Voltage: NA; Wattage: NA; Weight: 8mg; Datasheet: Y:\MIS_DATABASE\DATASHEETS\DISCRETES\TRANSISTORS_FETS\BSS138LT1G.PDF
R120 R121 R185 R380 R521-R526 = RESISTOR: RES 10K 1/16W 5% 0402; Chkd/date: VASANTHA/061216; Crtd /date: MAZHAR/230805; Custom_Duty: 15%; Customs_HS_Code: 85332119; Distributor_name: DIGIKEY; Distributor_part_number: 311-10KJRCT-ND; Footprint Path: Y:\MIS_DATABASE\Library\ALTIUM_TOOL\PCB_FOOTPRINTS\Altium_Footprint_Lib.PcbLib; Height: 0.40MM; Library Path: Y:\MIS_DATABASE\Library\ALTIUM_TOOL\SCHEMATICS_PARTS\MS_DISCRETE_Library.schlib; Mfr_name: YAGEO AMERICA; Mfr_part_number: RC0402JR-0710KL; Mistral Part No: 110011060021-R; Package: 0402; Part_type: RESISTORS\FIXED; Project: HSE; RoHS: RoHS; Temperature: -55°C+155°C; Tolerance: 5%; Voltage: NA; Wattage: 1/16W; Weight: 0.65mg; Datasheet: Y:\MIS_DATABASE\DATASHEETS\RESISTORS\RCXXXXL-SER_MAR18.PDF
R126 R563 = RESISTOR: RES 2.49K 1/16W 1% 0402; Chkd/date: VASANTHA/270516; Crtd /date: VASANTHA/270516; Custom_Duty: 15%; Customs_HS_Code: 85332119; Distributor_name: DIGIKEY; Distributor_part_number: 311-2.49KLRCT-ND; Footprint Path: Y:\MIS_DATABASE\Library\ALTIUM_TOOL\PCB_FOOTPRINTS\Altium_Footprint_Lib.PcbLib; Height: 0.40MM; Library Path: Y:\MIS_DATABASE\Library\ALTIUM_TOOL\SCHEMATICS_PARTS\MS_DISCRETE_Library.schlib; Mfr_name: YAGEO AMERICA; Mfr_part_number: RC0402FR-072K49L; Mistral Part No: 110016050020-R; Package: 0402; Part_type: RESISTORS\FIXED; Project: TMDXCSKCC; RoHS: RoHS; Temperature: -55°C+155°C; Tolerance: 1%; Voltage: NA; Wattage: 1/16W; Weight: 0.65mg; Datasheet: Y:\MIS_DATABASE\DATASHEETS\RESISTORS\RCXXXXL-SER_MAR18.PDF
R128 R135 R340 R341 R359 R363 R366 R385-R388 R562 = RESISTOR: RES 2.49K 1/16W 1% 0402; Assembly: DNI; Chkd/date: VASANTHA/270516; Crtd /date: VASANTHA/270516; Custom_Duty: 15%; Customs_HS_Code: 85332119; Distributor_name: DIGIKEY; Distributor_part_number: 311-2.49KLRCT-ND; Footprint Path: Y:\MIS_DATABASE\Library\ALTIUM_TOOL\PCB_FOOTPRINTS\Altium_Footprint_Lib.PcbLib; Height: 0.40MM; Library Path: Y:\MIS_DATABASE\Library\ALTIUM_TOOL\SCHEMATICS_PARTS\MS_DISCRETE_Library.schlib; Mfr_name: YAGEO AMERICA; Mfr_part_number: RC0402FR-072K49L; Mistral Part No: 110016050020-R; Package: 0402; Part_type: RESISTORS\FIXED; Project: TMDXCSKCC; RoHS: RoHS; Temperature: -55°C+155°C; Tolerance: 1%; Voltage: NA; Wattage: 1/16W; Weight: 0.65mg; Datasheet: Y:\MIS_DATABASE\DATASHEETS\RESISTORS\RCXXXXL-SER_MAR18.PDF
R316 R347 = RESISTOR: RES 220E 1/10W 5% 0402; Chkd/date: VASANTHA/291216; Crtd /date: GEETHA/260406; Custom_Duty: 15%; Customs_HS_Code: 85332119; Distributor_name: DIGIKEY; Distributor_part_number: P220JCT-ND; Footprint Path: Y:\MIS_DATABASE\Library\ALTIUM_TOOL\PCB_FOOTPRINTS\Altium_Footprint_Lib.PcbLib; Height: 0.40MM; Library Path: Y:\MIS_DATABASE\Library\ALTIUM_TOOL\SCHEMATICS_PARTS\MS_DISCRETE_Library.schlib; Mfr_name: PANASONIC-ECG; Mfr_part_number: ERJ-2GEJ221X; Mistral Part No: 110009030506-R; Package: 0402; Part_type: RESISTORS\FIXED; Project: RED EYE; RoHS: RoHS; Temperature: -55°C+155°C; Tolerance: 5%; Voltage: NA; Wattage: 1/10W; Weight: 0.8mg; Datasheet: Y:\MIS_DATABASE\DATASHEETS\RESISTORS\PAN-ERJSER_NOV17.PDF
R324 R343 R542-R548 = RESISTOR: RES 0E 1/16W JUMPER 0402; Chkd/date: VASANTHA/201216; Crtd /date: MUDDU/190810; Custom_Duty: 15%; Customs_HS_Code: 85332119; Distributor_name: DIGIKEY; Distributor_part_number: 541-0.0JCT-ND; Footprint Path: Y:\MIS_DATABASE\Library\ALTIUM_TOOL\PCB_FOOTPRINTS\Altium_Footprint_Lib.PcbLib; Height: 0.40MM; Library Path: Y:\MIS_DATABASE\Library\ALTIUM_TOOL\SCHEMATICS_PARTS\MS_DISCRETE_Library.schlib; Mfr_name: VISHAY; Mfr_part_number: CRCW04020000Z0ED; Mistral Part No: 110010080019-R; Package: 0402; Part_type: RESISTORS\FIXED; Project: PB_BUGBASE; RoHS: RoHS; Temperature: -55°C+155°C; Tolerance: NA; Voltage: NA; Wattage: 1/16W; Weight: 0.65mg; Datasheet: Y:\MIS_DATABASE\DATASHEETS\RESISTORS\CRCW0603.PDF
R349 = RESISTOR: RES 11K 1/16W 1% 0402; Chkd/date: VASANTHA/251115; Crtd /date: VASANTHA/251115; Custom_Duty: 15%; Customs_HS_Code: 85332119; Distributor_name: DIGIKEY; Distributor_part_number: 311-11.0KLRCT-ND; Footprint Path: Y:\MIS_DATABASE\Library\ALTIUM_TOOL\PCB_FOOTPRINTS\Altium_Footprint_Lib.PcbLib; Height: 0.40MM; Library Path: Y:\MIS_DATABASE\Library\ALTIUM_TOOL\SCHEMATICS_PARTS\MS_DISCRETE_Library.schlib; Mfr_name: YAGEO AMERICA; Mfr_part_number: RC0402FR-0711KL; Mistral Part No: 110015110012-R; Package: 0402; Part_type: RESISTORS\FIXED; Project: TI_VLAN_SWITCH; RoHS: RoHS; Temperature: -55°C+155°C; Tolerance: 1%; Voltage: NA; Wattage: 1/16W; Weight: 0.65mg; Datasheet: Y:\MIS_DATABASE\DATASHEETS\RESISTORS\RCXXXXL-SER_MAR18.PDF
R367 R369 R371 = RESISTOR: RES 10K 1/16W 5% 0402; Assembly: DNI; Chkd/date: VASANTHA/061216; Crtd /date: MAZHAR/230805; Custom_Duty: 15%; Customs_HS_Code: 85332119; Distributor_name: DIGIKEY; Distributor_part_number: 311-10KJRCT-ND; Footprint Path: Y:\MIS_DATABASE\Library\ALTIUM_TOOL\PCB_FOOTPRINTS\Altium_Footprint_Lib.PcbLib; Height: 0.40MM; Library Path: Y:\MIS_DATABASE\Library\ALTIUM_TOOL\SCHEMATICS_PARTS\MS_DISCRETE_Library.schlib; Mfr_name: YAGEO AMERICA; Mfr_part_number: RC0402JR-0710KL; Mistral Part No: 110011060021-R; Package: 0402; Part_type: RESISTORS\FIXED; Project: HSE; RoHS: RoHS; Temperature: -55°C+155°C; Tolerance: 5%; Voltage: NA; Wattage: 1/16W; Weight: 0.65mg; Datasheet: Y:\MIS_DATABASE\DATASHEETS\RESISTORS\RCXXXXL-SER_MAR18.PDF
R368 = RESISTOR: RES 2.2K 1/16W 5% 0402; Chkd/date: VASANTHA/061216; Crtd /date: BAVISH/021210; Custom_Duty: 15%; Customs_HS_Code: 85332119; Distributor_name: DIGIKEY; Distributor_part_number: 311-2.2KJRCT-ND; Footprint Path: Y:\MIS_DATABASE\Library\ALTIUM_TOOL\PCB_FOOTPRINTS\Altium_Footprint_Lib.PcbLib; Height: 0.40MM; Library Path: Y:\MIS_DATABASE\Library\ALTIUM_TOOL\SCHEMATICS_PARTS\MS_DISCRETE_Library.schlib; Mfr_name: YAGEO AMERICA; Mfr_part_number: RC0402JR-072K2L; Mistral Part No: 110010120018-R; Package: 0402; Part_type: RESISTORS\FIXED; Project: TE4; RoHS: RoHS; Temperature: -55°C+155°C; Tolerance: 5%; Voltage: NA; Wattage: 1/16W; Weight: 0.65mg; Datasheet: Y:\MIS_DATABASE\DATASHEETS\RESISTORS\RCXXXXL-SER_MAR18.PDF
R370 = RESISTOR: RES 2.2K 1/16W 5% 0402; Assembly: DNI; Chkd/date: VASANTHA/061216; Crtd /date: BAVISH/021210; Custom_Duty: 15%; Customs_HS_Code: 85332119; Distributor_name: DIGIKEY; Distributor_part_number: 311-2.2KJRCT-ND; Footprint Path: Y:\MIS_DATABASE\Library\ALTIUM_TOOL\PCB_FOOTPRINTS\Altium_Footprint_Lib.PcbLib; Height: 0.40MM; Library Path: Y:\MIS_DATABASE\Library\ALTIUM_TOOL\SCHEMATICS_PARTS\MS_DISCRETE_Library.schlib; Mfr_name: YAGEO AMERICA; Mfr_part_number: RC0402JR-072K2L; Mistral Part No: 110010120018-R; Package: 0402; Part_type: RESISTORS\FIXED; Project: TE4; RoHS: RoHS; Temperature: -55°C+155°C; Tolerance: 5%; Voltage: NA; Wattage: 1/16W; Weight: 0.65mg; Datasheet: Y:\MIS_DATABASE\DATASHEETS\RESISTORS\RCXXXXL-SER_MAR18.PDF
TP40 TP41 TP69 TP78 = TESTPOINT: TESTPOINT CIR 20 SMD; Chkd/date: SHREESHAIL/171006; Crtd /date: MAZHAR/171006; Custom_Duty: NA; Customs_HS_Code: NA; Distributor_name: NA; Distributor_part_number: NA; Footprint Path: Y:\MIS_DATABASE\Library\ALTIUM_TOOL\PCB_FOOTPRINTS\Altium_Footprint_Lib.PcbLib; Height: NA; Library Path: Y:\MIS_DATABASE\Library\ALTIUM_TOOL\SCHEMATICS_PARTS\MS_DISCRETE_Library.schlib; MECHANICAL 3D STEP FILE: NA; Mfr_name: LOCAL; Mistral Part No: NA; Package: SMD; Project: BT MODULE_CSRBC04; RoHS: NA; Temperature: NA; Tolerance: NA; Voltage: NA; Wattage: NA; Weight: NA; Datasheet: NA
U27 = TMUX154EDGSR_VSSOP10: IC ESD PROTECTED 2-CH 2:1 SWITCH WITH POWERED-OFF PROTECTION VSSOP10; Chkd/date: MANIRAJA/040918; Crtd /date: MANIRAJA/040918; Custom_Duty: 15%; Customs_HS_Code: 85423100; Distributor_name: DIGIKEY; Distributor_part_number: 296-48347-1-ND; Footprint Path: Y:\MIS_DATABASE\Library\ALTIUM_TOOL\PCB_FOOTPRINTS\Altium_Footprint_Lib.PcbLib; Height: 1.10MM; Library Path: Y:\MIS_DATABASE\Library\ALTIUM_TOOL\SCHEMATICS_PARTS\MS_ANALOG-APPLICATION_Library.schlib; Mfr_name: TEXAS INSTRUMENTS; Mistral Part No: 140118090001-R; Package: VSSOP10; Part_type: ICS\ANALOG\SWITCH; Project: DLRL_DFP_ATRUC CARD; RoHS: RoHS; Temperature: -40°C+85°C; Tolerance: NA; Voltage: NA; Wattage: NA; Weight: NA; Datasheet: Y:\MIS_DATABASE\DATASHEETS\ICS\ANALOG\TMUX154EXXX.PDF
U31 = SN74LVC1G08DBVRE4_SOT23-5: IC SINGLE 2-INPUT POSITIVE AND GATE SOT23-5; Chkd/date: SUHAS/221010; Crtd /date: USMAN/151008; Custom_Duty: 15%; Customs_HS_Code: 85423100; Distributor_name: DIGIKEY; Distributor_part_number: SN74LVC1G08DBVRE4-ND; Height: 1.45MM; Mfr_name: TEXAS INSTRUMENTS; Mistral Part No: 141009060026-R; Part_type: ICS\DIGITAL\GATES; Project: KHAN_MAIN; RoHS: Sb/ Br FREE; Temperature: -40°C+85°C; Datasheet: Y:\MIS_DATABASE\DATASHEETS\ICS\DIGITAL\GATES\SN74LVC1G08.PDF
U80 = DP83869HM_VQFN48: IC ETHERNET TRANSCEIVER 10/100/1000 WITH COPPER AND FIBRE INTERFACE VQFN48; Chkd/date: MANIRAJA/060519; Crtd /date: ALVY/060519; Custom_Duty: 15%; Customs_HS_Code: 85423100; Distributor_name: DIGIKEY; Distributor_part_number: 296-53377-1-ND; Footprint Path: Y:\MIS_DATABASE\Library\ALTIUM_TOOL\PCB_FOOTPRINTS\Altium_Footprint_Lib.PcbLib; Height: 1.00MM; Library Path: Y:\MIS_DATABASE\Library\ALTIUM_TOOL\SCHEMATICS_PARTS\MS_TELECOM_Library.schlib; Mfr_name: TEXAS INSTRUMENTS; Mistral Part No: 143019050002-R; Package: VQFN48; Part_type: ICS\TELECOM\TRANSCEIVER; Project: J7ES_ENET_DP83869HM_EXP; RoHS: RoHS; Temperature: -40°C+125°C; Tolerance: NA; Voltage: NA; Wattage: NA; Weight: NA; Datasheet: Y:\MIS_DATABASE\DATASHEETS\ICS\TELECOM\DP83869HM.PDF
J38 = CON_FLEX_40X1_FH12A-40S-0.5SH: CON FPC 40X1 0.50MM PITCH RT TOP SMD; Chkd/date: SHREESHAIL/201106; Crtd /date: MAZHAR/171106; Custom_Duty: 24%; Customs_HS_Code: 85369090; Distributor_name: DIGIKEY; Distributor_part_number: HFK40CT-ND; Height: 2.00MM; Mfr_name: HIROSE ELECTRIC EUROPE; Mfr_part_number: FH12A-40S-0.5SH(55); Mistral Part No: 150009030176-R; Package: SMD; Part_type: CONNECTOR\FPC; Project: PMP LCD BOARD; Datasheet: Y:\MIS_DATABASE\DATASHEETS\CONNECTORS\FH12SERIES.PDF
R494 R495 R550 R551 = RESISTOR: RES 4.7K 1/16W 5% 0402; Chkd/date: VASANTHA/130516; Crtd /date: VASANTHA/130516; Custom_Duty: 15%; Customs_HS_Code: 85332119; Distributor_name: DIGIKEY; Distributor_part_number: 311-4.7KJRCT-ND; Footprint Path: Y:\MIS_DATABASE\Library\ALTIUM_TOOL\PCB_FOOTPRINTS\Altium_Footprint_Lib.PcbLib; Height: 0.40MM; Library Path: Y:\MIS_DATABASE\Library\ALTIUM_TOOL\SCHEMATICS_PARTS\MS_DISCRETE_Library.schlib; Mfr_name: YAGEO AMERICA; Mfr_part_number: RC0402JR-074K7L; Mistral Part No: 110011060001-R; Package: 0402; Part_type: RESISTORS\FIXED; Project: TMDXCSK368; RoHS: RoHS; Temperature: -55°C+155°C; Tolerance: 5%; Voltage: NA; Wattage: 1/16W; Weight: 0.65mg; Datasheet: Y:\MIS_DATABASE\DATASHEETS\RESISTORS\RCXXXXL-SER_MAR18.PDF
U51 = TCA9617BDGKR_VSSOP8: IC FM+I2C BUS REPEATER LEVEL TRANSLATOR VSSOP8; Chkd/date: MANIRAJA/131017; Crtd /date: MANIRAJA/131017; Custom_Duty: 15%; Customs_HS_Code: 85423100; Distributor_name: DIGIKEY; Distributor_part_number: 296-40579-1-ND; Height: 1.10MM; Mfr_name: TEXAS INSTRUMENTS; Mistral Part No: 141017100010-R; Package: VSSOP8; Part_type: ICS\INTERFACE\LEVEL TRANSLATOR; Project: TI_MAXIE_CPB; RoHS: RoHS; Temperature: -40°C+85°C; Tolerance: NA; Voltage: NA; Wattage: NA; Weight: NA; Datasheet: Y:\MIS_DATABASE\DATASHEETS\ICS\INTERFACE\TCA9617B.PDF
1 = PCB: AM64x EVM Bare PCB
ACC1-ACC3 ACC7 ACC8 = ACCESSORY: ACCESSORIE JUMPER SHORTING GOLD FLASH; Chkd/date: SUHAS\211010; Crtd /date: USMAN/301208; Distributor_name: DIGIKEY; Distributor_part_number: S9001-ND; Footprint Path: Y:\MIS_DATABASE\Library\ALTIUM_TOOL\PCB_FOOTPRINTS\Altium_Footprint_Lib.PcbLib; Library Path: Y:\MIS_DATABASE\Library\ALTIUM_TOOL\SCHEMATICS_PARTS\MS_MECHANICAL_Library.schlib; Mfr_name: SULLINS CONNECTOR; Mistral Part No: 160009030153-R; Part_type: ACCESSORIES; Project: SMART VIEW_NVR; RoHS: RoHS; Temperature: -55°C+105°C; Datasheet: Y:\MIS_DATABASE\DATASHEETS\MISC\MODULES\SPC02SYAN.PDF
ACC4 = ACCESSORY: ACCESSORIE CONNECTOR SHUNT 2X3 POS EDGE MOUNT SOCKET STRIP; Chkd/date: MANIRAJA/141117; Crtd /date: MANIRAJA/141117; Distributor_name: DIGIKEY; Distributor_part_number: SAM10620-ND; Mfr_name: SAMTEC; Mistral Part No: 160017110050-R; Part_type: ACCESSORIES; Project: TI_MAXIE_CPB; RoHS: RoHS; Temperature: -55°C+125°C; Datasheet: Y:\MIS_DATABASE\DATASHEETS\MISC\ACCESSORIES\SAMTEC-MNT-SER.PDF
ACC10 = ACCESSORY: ACCESSORIE BGA SOCKET AM64x MICROPROCESSOR BGA441; Chkd/date: MANIRAJA/220620; Crtd /date: ALVY/220620; Custom_Duty: NA; Customs_HS_Code: NA; Distributor_name: NA; Distributor_part_number: NA; Footprint Path: NA; Height: 10.93MM; Library Path: NA; Mfr_name: IRONWOOD ELECTRONICS; Mistral Part No: 160020060058; Package: BGA441; Part_type: ACCESSORIES; Project: AM64x-GP_EVM BRD; RoHS: NA; Temperature: -55°C+160°C; Tolerance: NA; Voltage: NA; Wattage: NA; Weight: 39530mg; Datasheet: Y:\MIS_DATABASE\DATASHEETS\MISC\ACCESSORIES\C19874_MAY20.PDF
ACC11 = ACCESSORY: ACCESSORIE TI EVM FLYERS STANDARD TERMS AND CONDITIONS; Chkd/date: MANIRAJA/221020; Crtd /date: ALVY/211020; Mfr_name: TEXAS INSTRUMENTS; Mistral Part No: 160020100056; Part_type: ACCESSORIES; Project: AM64x-IO LINK BRD
ACC12 = ACCESSORY: ACCESSORIE TI EVM FLYERS STANDARD WARRANTY NOTICE-BLACK AND WHITE; Chkd/date: MANIRAJA/221020; Crtd /date: ALVY/211020; Mfr_name: TEXAS INSTRUMENTS; Mistral Part No: 160020100057; Part_type: ACCESSORIES; Project: AM64x-IO LINK BRD
FID1-FID3 = Fiducial
LBL1-LBL3 = ACCESSORY_THT-3-423-10: ACCESSORIE 1 WORKHORSE POLYSTER LABLE 0.25" X 1"; Chkd/date: MANIRAJA/270218; Crtd /date: ALVY/260218; Footprint Path: Y:\MIS_DATABASE\Library\ALTIUM_TOOL\PCB_FOOTPRINTS\Altium_Footprint_Lib.PcbLib; Library Path: Y:\MIS_DATABASE\Library\ALTIUM_TOOL\SCHEMATICS_PARTS\MS_MECHANICAL_Library.schlib; Mfr_name: BRADY; Mistral Part No: 160018020185; Part_type: ACCESSORIES; Project: TI_MAXIE_CPB
Logo1 Logo3 Logo4 = TI_Logo
Logo2 = FCC_disclaimer
M1-M6 = ACCESSORY: ACCESSORIE RECESSED BUMPER 19.05MM DIA; Chkd/date: MANIRAJA/110718; Crtd /date: MANIRAJA/110718; Distributor_name: DIGIKEY; Distributor_part_number: 36-728-ND; Mfr_name: KEYSTONE; Mistral Part No: 160018070042-R; Part_type: ACCESSORIES; Project: TI_MAXIE_CPB; RoHS: RoHS; Weight: 2042mg; Datasheet: Y:\MIS_DATABASE\DATASHEETS\MISC\ACCESSORIES\728.PDF
M10-M14 M19 = WASHER_PLAIN: PLAIN WASHER FOR M3 SS-316; Chkd/date: MANIRAJA/190218; Crtd /date: MANIRAJA/190218; Distributor_name: DIGIKEY; Distributor_part_number: 36-4692-ND; Footprint Path: Y:\MIS_DATABASE\Library\ALTIUM_TOOL\PCB_FOOTPRINTS\Altium_Footprint_Lib.PcbLib; Library Path: Y:\MIS_DATABASE\Library\ALTIUM_TOOL\SCHEMATICS_PARTS\MS_MECHANICAL_Library.schlib; Mfr_name: KEYSTONE; Mfr_part_number: 4692; Mistral Part No: 160018020078-R; Package: SS; Part_type: MECHANICAL\WASHERS; Project: TI_MAXIE_CPB; RoHS: RoHS; Datasheet: Y:\MIS_DATABASE\DATASHEETS\MISC\MECHANICAL\4692.PDF
MH1-MH6 = HEX_SPACER_FF: HEX SPACER FEMALE TO FEMALE M2.5 X 30MM; Chkd/date: MANIRAJA/190218; Crtd /date: MANIRAJA/190218; Distributor_name: DIGIKEY; Distributor_part_number: 732-10626-ND; Footprint Path: Y:\MIS_DATABASE\Library\ALTIUM_TOOL\PCB_FOOTPRINTS\Altium_Footprint_Lib.PcbLib; Height: 30.00MM; Library Path: Y:\MIS_DATABASE\Library\ALTIUM_TOOL\SCHEMATICS_PARTS\MS_MECHANICAL_Library.schlib; Mfr_name: WURTH ELECTRONICS; Mfr_part_number: 970300151; Mistral Part No: 160018020071-R; Package: SS; Part_type: MECHANICAL\SPACER; Project: TI_MAXIE_CPB; RoHS: RoHS; Datasheet: Y:\MIS_DATABASE\DATASHEETS\MISC\MECHANICAL\970XXX1.PDF
MH13-MH18 = SCREW_PAN: PHILLIPS PAN HEAD SCREW - M2.5 X 4 SS-316; Chkd/date: MANIRAJA/190218; Crtd /date: MANIRAJA/190218; Distributor_name: DIGIKEY; Distributor_part_number: 36-29300-ND; Footprint Path: Y:\MIS_DATABASE\Library\ALTIUM_TOOL\PCB_FOOTPRINTS\Altium_Footprint_Lib.PcbLib; Height: 4.00MM; Library Path: Y:\MIS_DATABASE\Library\ALTIUM_TOOL\SCHEMATICS_PARTS\MS_MECHANICAL_Library.schlib; Mfr_name: KEYSTONE; Mfr_part_number: 29300; Mistral Part No: 160018020076-R; Package: SS; Part_type: MECHANICAL\SCREWS; Project: TI_MAXIE_CPB; RoHS: RoHS; Datasheet: Y:\MIS_DATABASE\DATASHEETS\MISC\MECHANICAL\29300.PDF
MH19-MH24 = SCREW_PAN: PHILLIPS PAN HEAD SCREW - M2.5 X 12; Chkd/date: MANIRAJA/110718; Crtd /date: MANIRAJA/110718; Distributor_name: DIGIKEY; Distributor_part_number: 36-29304-ND; Height: 12.00MM; Mfr_name: KEYSTONE; Mfr_part_number: 29304; Mistral Part No: 160018070043-R; Part_type: ACCESSORIES; Project: TI_MAXIE_CPB; RoHS: RoHS; Datasheet: Y:\MIS_DATABASE\DATASHEETS\MISC\MECHANICAL\29304.PDF

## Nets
DGND: C89.2 C99.2 C101.2 C104.2 C105.2 C106.2 C110.2 C111.2 C112.2 C114.2 C124.2 C128.2 C161.2 C181.2 C385.2 C389.2 C392.2 C394.2 C395.2 C397.2 C401.2 C469.2 C472.2 J38.7 J38.16 J38.25 J38.34 J38.40 J38.41 J38.42 Q14.2(S) Q16.2(S) R120.2 R121.2 R135.2 R341.2 R349.1 R359.2 R363.2 R367.2 R371.2 R385.2 R386.2 R563.2 U27.5(GND) U31.3(GND) U51.4(GND) U80.49(GND) ; also on sheet 2 3 4 5 6 7 8 9 10 11 12 13 14 15 16 17 18 19 20 21 22 23 24 25 26 27 28 29 40
VCC3V3_TA: C181.1 C469.1 C472.1 J38.1 J38.2 J38.3 R185.2 R494.1 R495.1 R521.2 R522.2 R523.2 R524.2 R525.2 R526.2 R550.1 R551.1 U51.1(VCCA) ; also on sheet 16 17 29
VCC_3V3_SYS: C89.1 C99.1 C101.1 C104.1 C128.1 C161.1 C385.1 C389.1 FB19.1 R126.1 R128.1 R316.1 R340.1 R347.1 R366.1 R368.2 R369.1 R370.2 R380.2 R387.1 R388.1 R562.1 U27.10(VCC) U31.5(VCC) U51.8(VCCB) U80.18(VDDIO) U80.30(VDDIO) ; also on sheet 2 5 6 7 8 10 11 12 13 14 15 16 17 18 19 20 21 23 24 25 26 27 29 40
VDD_1V1: C105.1 C110.1 C112.1 C124.1 C394.1 C395.1 C401.1 U80.6(VDDA1P1) U80.31(VDD1P1) U80.39(VDD1P1) ; also on sheet 16 40
VDD_2V5: C106.1 C111.1 C114.1 C392.1 C397.1 U80.3(VDDA2P5) U80.9(VDDA2P5) ; also on sheet 2 16 40
BOOTMODE_I2C_SCL: J38.37 R550.2 ; also on sheet 29
BOOTMODE_I2C_SDA: J38.39 R551.2 ; also on sheet 29
CPSW_RGMII1_MDC: U27.7(B1) ; also on sheet 2
CPSW_RGMII1_MDIO: U27.3(A1) ; also on sheet 2
GPIO_RGMII2_RST: R371.1 R380.1 U31.1(A) ; also on sheet 13
PORz_OUT: U31.2(B) ; also on sheet 2 12 24 29 40
PRG1_ETH2_D0M: J21.B3 U80.2(TD_M_A)
PRG1_ETH2_D0P: J21.B2 U80.1(TD_P_A)
PRG1_ETH2_D1M: J21.B7 U80.5(TD_M_B)
PRG1_ETH2_D1P: J21.B4 U80.4(TD_P_B)
PRG1_ETH2_D2M: J21.B6 U80.8(TD_M_C)
PRG1_ETH2_D2P: J21.B5 U80.7(TD_P_C)
PRG1_ETH2_D3M: J21.B9 U80.11(TD_M_D)
PRG1_ETH2_D3P: J21.B8 U80.10(TD_P_D)
PRG1_ETH2_GPIO_1: R340.2 R341.1 U80.22(JTAG_TDO/GPIO_1)
PRG1_ETH2_LED1: J21.B13 Q14.3(D)
PRG1_ETH2_LED3: J21.B12 Q16.3(D)
PRG1_ETH2_LED_1000/RX_ER: R343.2 R386.1 R388.2 U80.46(LED_1/RX_ER) ; also on sheet 18
PRG1_ETH2_LED_ACT: R324.1 R385.1 R387.2 U80.45(LED_2/GPIO_0)
PRG1_ETH2_LED_LINK: R562.2 R563.1 U80.47(LED_0) ; also on sheet 18
PRG1_MDIO_MDC: U27.8(B0) ; also on sheet 18 40
PRG1_MDIO_MDIO: U27.2(A0) ; also on sheet 18 40
PRG1_RGMII2_ETH2_CLK: U80.20(XI) ; also on sheet 11
PRG1_RGMII2_ETH2_CLK_OUT: TP78.1(TP) U80.40(CLK_OUT)
PRG1_RGMII2_ETH2_RBIAS: R349.2 U80.12(RBIAS)
PRG1_RGMII2_FET_ENn: R121.1 U27.9(~{EN})
PRG1_RGMII2_FET_SEL: R120.1 U27.1(SEL) ; also on sheet 13
PRG1_RGMII2_MDC: R369.2 U27.6(B) U80.42(MDC)
PRG1_RGMII2_MDIO: R370.1 U27.4(A) U80.41(MDIO)
PRG1_RGMII2_RD0: R126.2 R359.1 U80.33(RX_D0) ; also on sheet 18
PRG1_RGMII2_RD1: R128.2 R363.1 U80.34(RX_D1) ; also on sheet 18
PRG1_RGMII2_RD2: U80.35(RX_D2) ; also on sheet 18
PRG1_RGMII2_RD3: U80.36(RX_D3) ; also on sheet 18
PRG1_RGMII2_RESETn: R367.1 U31.4(Y) U80.43(RESET_N)
PRG1_RGMII2_RX_CTL: R135.1 R366.2 U80.38(RX_CTRL/RX_DV) ; also on sheet 18
PRG1_RGMII2_RXC: U80.32(RX_CLK) ; also on sheet 18
PRG1_RGMII2_TD0: U80.28(TX_D0) ; also on sheet 18
PRG1_RGMII2_TD1: U80.27(TX_D1) ; also on sheet 18
PRG1_RGMII2_TD2: U80.26(TX_D2) ; also on sheet 18
PRG1_RGMII2_TD3: U80.25(TX_D3) ; also on sheet 18
PRG1_RGMII2_TX_CTL: U80.37(TX_CTRL/TX_EN) ; also on sheet 18
PRG1_RGMII2_TXC: U80.29(GTX_CLK/TX_CLK) ; also on sheet 18
PRG1_RGMII_INTn: R368.1 U80.44(INT_N/PWDN_N) ; also on sheet 2 12 40
SoC_I2C1_SCL: U51.7(SCLB) ; also on sheet 5 6 7 10 13 14
SoC_I2C1_SDA: U51.6(SDAB) ; also on sheet 5 6 7 10 13 14
SoC_I2C1_TA_SCL: J38.36 R495.2 U51.2(SCLA)
SoC_I2C1_TA_SDA: J38.38 R494.2 U51.3(SDAA)
TEST_GPIO1: R523.1 R545.1 ; also on sheet 25
TEST_GPIO2: R524.1 R546.1 ; also on sheet 13
TEST_GPIO3: R525.1 R547.1 TP41.1(TP) ; also on sheet 29
TEST_GPIO4: R526.1 R548.1 TP40.1(TP) ; also on sheet 29
TEST_PORZn: R521.1 R543.1 ; also on sheet 25
TEST_POWERDOWN: R542.1 ; also on sheet 17
TEST_WARMRESETn: R522.1 R544.1 ; also on sheet 25
N15365714: J38.27 R543.2
N15365947: J38.30 R545.2
N15366015: J38.31 R546.2
N15366091: J38.32 R547.2
N17211229: J38.33 R548.2
N17546132: J38.26 R542.2
N17546158: J38.28 R544.2
N18117332: Q14.1(G) R324.2
N18117389: Q16.1(G) R343.1
N24754956: TP69.1(TP) U80.13(VDDA1P8_1) U80.48(VDDA1P8_2)
N26442461: R185.1 U51.5(EN)
N27217693: FB19.2 J21.B1
N27218001: J21.B14 R316.2
N27218087: J21.B11 R347.2

Not connected (* = marked no-connect by the designer): J21 B10(NC2)*; J38 4* 5* 6* 8* 9* 10* 11* 12* 13* 14* 15* 17* 18* 19* 20* 21* 22* 23* 24* 29* 35*; U80 14(SON)* 15(SOP)* 16(SIP)* 17(SIN)* 19(XO)* 21(JTAG_CLK/TX_ER)* 23(JTAG_TMS)* 24(JTAG_TDI/SD)*

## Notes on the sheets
sheet 30
- TEST AUTOMATION
- 40-PIN AUTOMATION HEADER
- TEST AUTOMATION  GPIO MAPPING
- Internal/
  External
  PU/PD states
- Direction WRT CTRL
- SIGNAL NAME
- DESCRIPTION
- TEST_POWERDOWN
  TEST_PORZn
  TEST_WARMRESETn
  TEST_GPIO1
  TEST_GPIO2
  TEST_GPIO3
  TEST_GPIO4
- Used to Power down the OVP Circuit
  Used to  Reset the SoC PORz
  Used to Reset the SoC Warmreset
  Used to Generate the interrupt on
  GPIO0_13_INTn Pin
  Connected to I/O Expander to Communicate
  with SoC
  Used to Enable the BOOTMODE Buffer
  Used to Reset the Bootmode IO Expander
- OUTPUT
  OUTPUT
  OUTPUT
  OUTPUT
  OUTPUT
  OUTPUT
  OUTPUT
- External Pullup
  External Pullup
  External Pullup
  External Pullup
  External Pullup
  External Pullup
  External Pullup
- Off Page Connections
- To Processor
- To Bootmode
  Buffer
- To Debounce Ckt
- To High Side SW
- To Debounce Ckt
- To Debounce Ckt
- To IO Expander
- To EN Boot Mode Buffer
- To RST Boot Mode Buffer
sheet 31
- HARDWARE SCHEMATICS
- SCREWS
- JUMPERs
- STANDOFFs
- ASSEMBLY NOTES
- 1. All MSL components should be baked as per JEDEC standard.
  2. PCB should be baked at 120 degree for 8 hours.
  3. Board assembly must comply with workmanship standards.
  IPC-A-610 Class 2, unless otherwise specified.
  4. These assemblies are ESD sensitive, ESD precautions
  shall be observed.
  5. These assemblies must be clean and free from flux and
  all contaminants. Use of no clean flux is not acceptable.
  6. Provide serial numbers to the assembled boards for identification.
  7. The assembled board are wrapped in ESD Covers(individual) and
  packed securely before shipment.
- WASHER's
- FIDUCIALS
- RUBBER FEET
- TI EVM FLYERS
- AM64x Socket
- Assembled PCB
- BARE PCB
- LABELS
- LOGOs
- ORDERABLE PART NO
- Texas Intruments
- For Evaluation only; not FCC approved for resale
- WEEE Mark
- CE Mark
- Board Serial No.
- Orderable part number
- Variant
- Label Text
- 001
- TMDS64GPEVM
- Assembly Revision
sheet 32
- GPIO  MAPPING TABLE
sheet 33
- I2C TREE
sheet 34
- POWER SEQUENCE
- POWER UP SEQUENCE
- 12V
- 5V0
- 3V3_PREREG
- 3V3_SYS
- 2V5 ,2V8
- 1V0 ,1V1
- 1V8
- 1V8 ANALOG
- 1V2
- 0V75
- 0V85
- MCU_PORz
- POWER DOWN SEQUENCE
- 5V0
- 3V3_SYS,2V5,
  1V1 ,1V0
- 1V8 ANALOG,
  1V8_IO,2V8
- 1V2
- 0V85
- 0V75
- MCU_PORz
- 3V3_PREREG
sheet 35
- POWER FLOW DIAGRAM
- CORE SUPPLY
- ARRAY CORE SUPPLY
- STEERING RESISTORS
- 0.75 VDD_CORE
- 0.85 VDDR_CORE&OTHERS
- R2 & R4 INSTALLED
- 0.8 VDD_CORE
- 0.85 VDDR_CORE&OTHERS
- R2 & R4 INSTALLED
- 0.8 VDD_CORE & OTHERS
- 0.85 VDDR_CORE
- R1 & R4 INSTALLED
- 0.85 VDD_CORE,VDDR_CORE&OTHERS
- NONE
- R1 & R3 INSTALLED
sheet 36
- BLOCK DIAGRAM_AM64x_EVM
sheet 37
- AM64x GENERAL PURPOSE EVM BOARD
- TMDS64GPEVM
- TABLE OF CONTENTS
- PAGE
- CONTENTS
- PAGE
- CONTENTS
- REV
- E2
- 01
- TABLE OF CONTENTS
- 35
- DEBOUNCE CIRCUIT & VOLTAGE SUPERVISOR
- VER
- 1.05
- 02
- REVISION HISTORY
- 36
- MAIN INPUT 12V DC
- 03
- BLOCK DIAGRAM AM64x EVM BOARD
- 37
- DUAL & PRE_REG POWER SUPPLY
- 04
- BLOCK DIAGRAM - XDS110
- 38
- SoC POWER SUPPLY
- 05
- POWER FLOW DIAGRAM
- 39
- PERIPHERAL POWER SUPPLY
- 06
- POWER SEQUENCE
- 40
- HARDWARE SCHEMATICS
- 07
- GPIO MAPPING TABLE
- 08
- I2C TREE
- 09
- SOC POWER
- 10
- SOC POWER CAPS
- 11
- SOC VSS
- 12
- DDR INTERFACE
- 13
- eMMC FLASH AND SDCARD INTERFACE
- 14
- OSPI FLASH
- 15
- EEPROM,PRESENCE DETECTION & TEMP SENSOR
- 16
- CPSW RGMII_1 ETHERNET PHY
- 17
- ICSSG RGMII_2 ETHERNET PHY
- 18
- ICSSG RGMII_1 ETHERNET PHY
- 19
- TEST AUTOMATION
- 20
- BOOT MODE BUFFER & SWITCHES
- 21
- CURRENT MONITORING DEVICES
- 22
- XDS110  DEBUGGER
- 23
- JTAG BUFFER
- 24
- MIPI 60 PIN CONNECTOR
- 25
- USB 2.0 INTERFACE
- 26
- FT4232 UART TO USB BRIDGE
- 27
- HSE BOARD CONNECTOR
- 28
- GPMC & FSI CONNECTOR
- 29
- CAN & DISPLAY INTERFACE
- 30
- PCIe INTERFACE
- 31
- ETHERNET PHY  CLOCK GENERATOR
- 32
- ETHERNET LEDs
- 33
- IO EXPANDER & TEST HEADER
- 34
- MCU GENERAL&SAFETY CONNECTOR
sheet 38
- REVISION HISTORY
- VER #
- DATE
- DESCRIPTION OF CHANGES
- AUTHOR
- REVIEWED  BY
- APPROVED  BY
- 1.0
- 10th AUGUST 2020
- Drafted from "PROC101E1_SCH" document.
- Mistral Design Team
- AJIT MB
- AJIT MB
- 1.01
- 11th AUGUST 2020
- Power Sequence changed as Per power down sequence mentioned in AM64x Data manual
- Mistral Design Team
- AJIT MB
- AJIT MB
- 1.02
- 13th AUGUST 2020
- 1.U74 Monitoring changed from 12V to 5V
  2. U103 OR gate and U104 AND gate added to ensure the power down sequence
  is followed as mentioned in the data manual
  3.R260,R266 values changed to monitor 5V
  4.U35 changed to 3 input AND gate
  5.Q20 added to provide MCU_PORz to SD enable
  6.R131 changed from 100k to 10k resistor
  7.C486 , 10uF added to U25 regulator output VCC_CORE
  8.R539,R284,R293 removed
  9.Inductor Values, Current Sense Resistor Value & compensation circuit changed
  in LM5140 section
- Mistral Design Team
- AJIT MB
- AJIT MB
- 1.Added series resistor option for OSPI_LBCLK0 to connect to DS of OSPI Memory
  2. Added LPF filters for SoC_I2C0_SCL, SoC_I2C0_SDA, MCU_I2C0_SCL,
  SoC_I2C0_SDA and PRG1_RGMII_INTn signals
  3. Changed C70 470uF capacitor to Electrolytic Polymer CAP
  4. Added series resistors R577 to R589 to EN pins of all Power IC's
  5. Deleted Net Name CAP_VDDSHV_MMC1
  6. Changed Net SoC_PORz to PORz
  7. R314 Pull-up changed from VCC3V3_PREREG to VCC_3V3_SYS
  8. U72 input voltage changed from VCC_3V3_SYS to  VCC3V3_PREREG
  9. TEST_LED1 is connected to IO Expander pin P20
- 1.03
- 14th AUGUST 2020
- Mistral Design Team
- AJIT MB
- AJIT MB
- 1.04
- 2nd SEPTEMBER 2020
- 1.Enable for U100 changed from VIN_MON_PORz_3V3_PG to VCC3V3_SYS_PG
  2.Voltage divider provided to monitor VMAIN and VCC_5V0 for VDDA_SYS_MON
  3.Net name VDDA_MCU_ADC changed to VDDA_ADC
  4. Series Resistors R592 & R601 for OSPI DQS Removed
  5. Resistors RA6, R391 & R392 made DNI
- Mistral Design Team
- AJIT MB
- AJIT MB
sheet 39
- ICSSG1 - RGMII 2
- Dual RJ45 CON With Integrated Magnetics
- Decaps
- STRAPPING RESISTORS
- PRG1 ETH2 RESET
- PHY ADDRESS = 00011
- Auto-negotiation, 10/100/1000 advertised, Auto-MDI-X
- RGMII to Copper (1000BaseT/100Base-TX/10Base-Te)
- Off Page Connections
- PRG1 MDC/MDIO FET SWITCH
- To Processor
- PRG1_ETHERNET - 2 SPEED & ACTIVITY  LED 's DRIVERS
- From Processor
- From CPSW SW
- From IO Expander
- TMUX154EDGSR Truth Table
- From Clock Buffer
